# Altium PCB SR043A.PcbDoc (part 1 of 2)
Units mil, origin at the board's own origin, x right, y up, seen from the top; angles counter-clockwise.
Board outline 3937.01 x 3543.31 mil, 6 copper layers (Top Layer, Signal Layer 1, Signal Layer 2, Signal Layer 3, Signal Layer 4, Bottom Layer), stack 60.536 mil thick; 120 components, 36 nets, 230 pads, 513 vias.
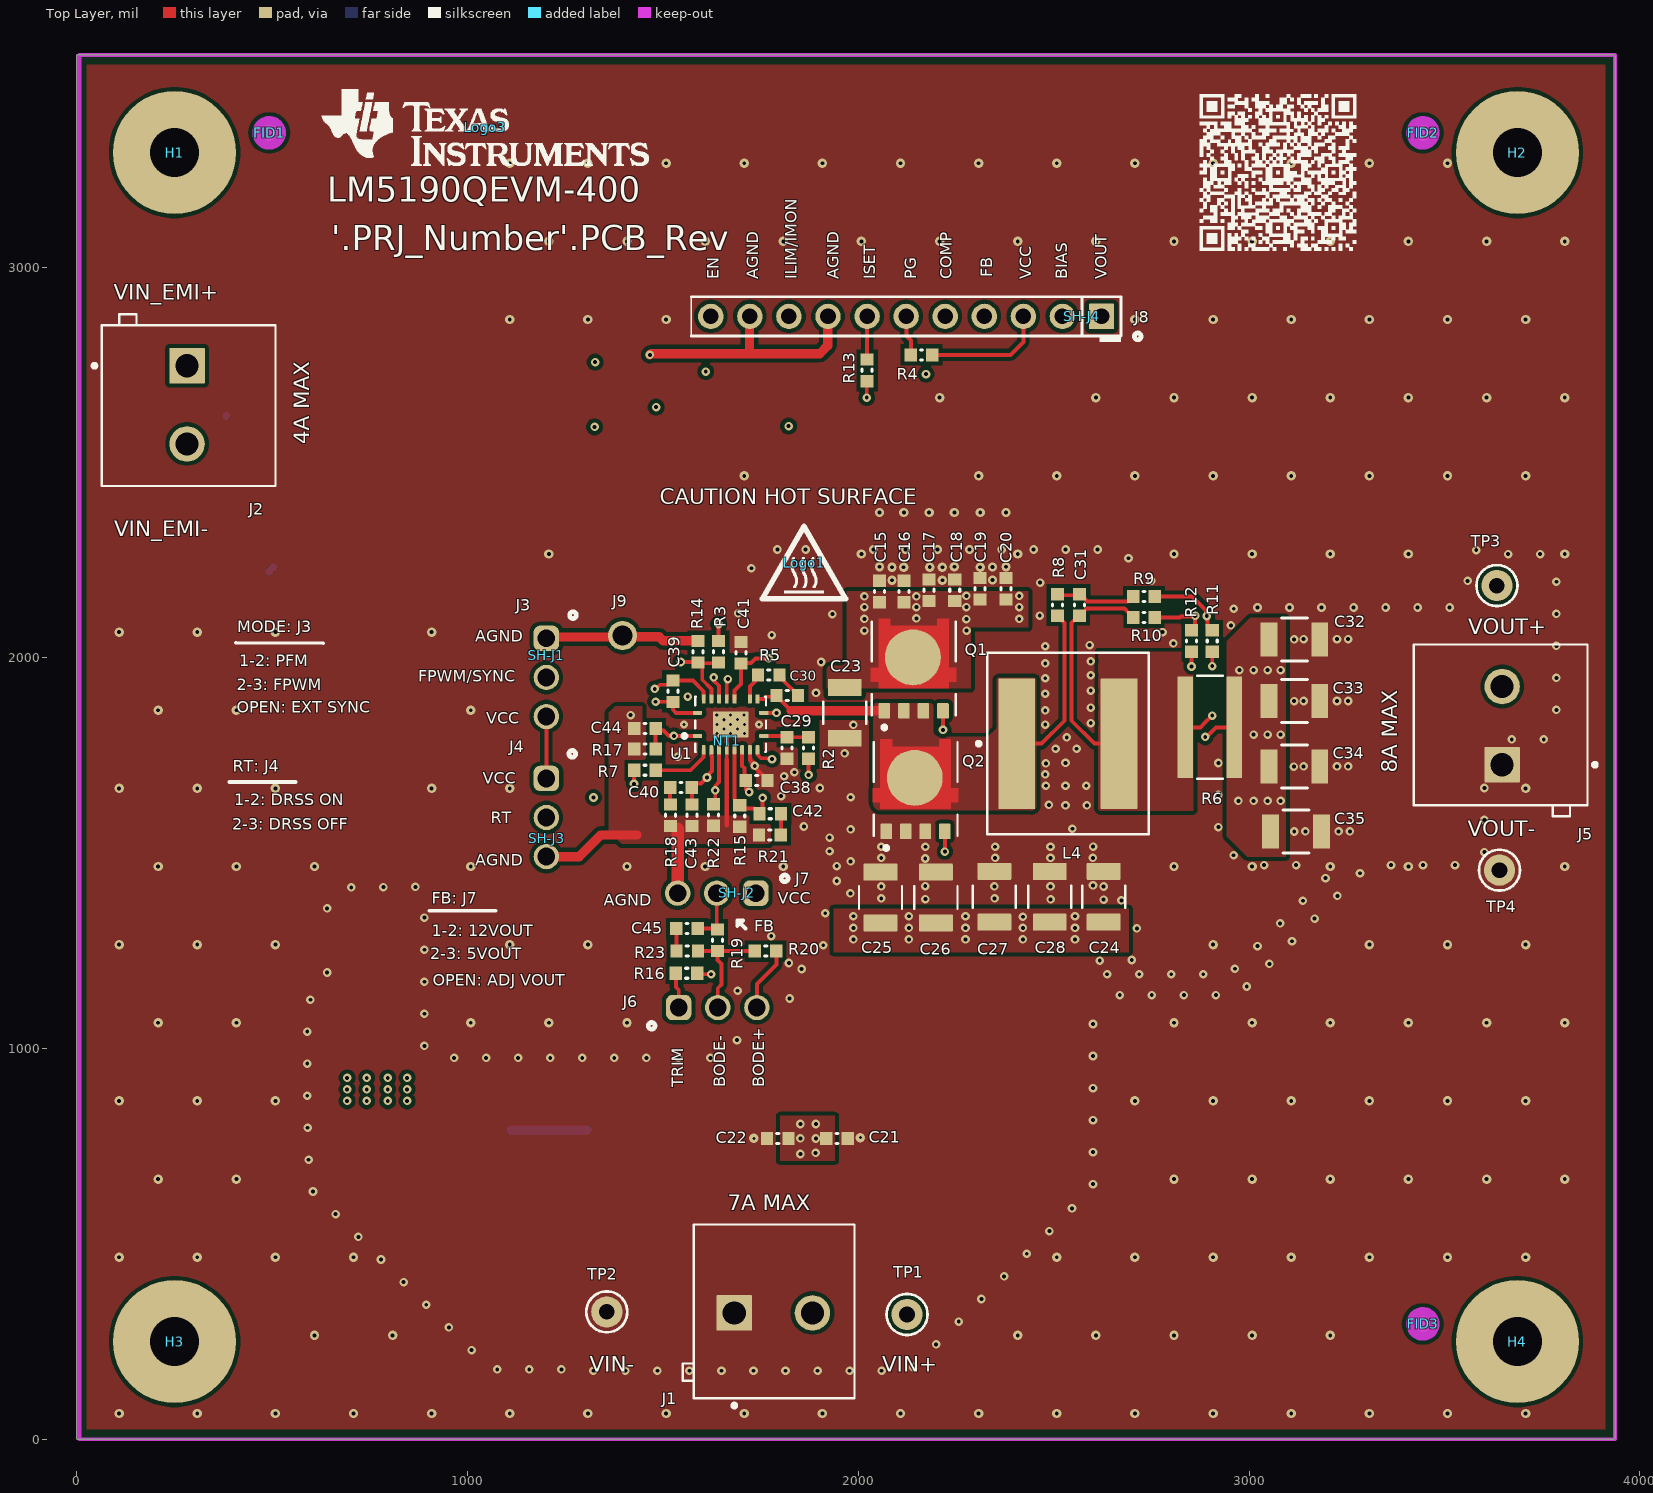
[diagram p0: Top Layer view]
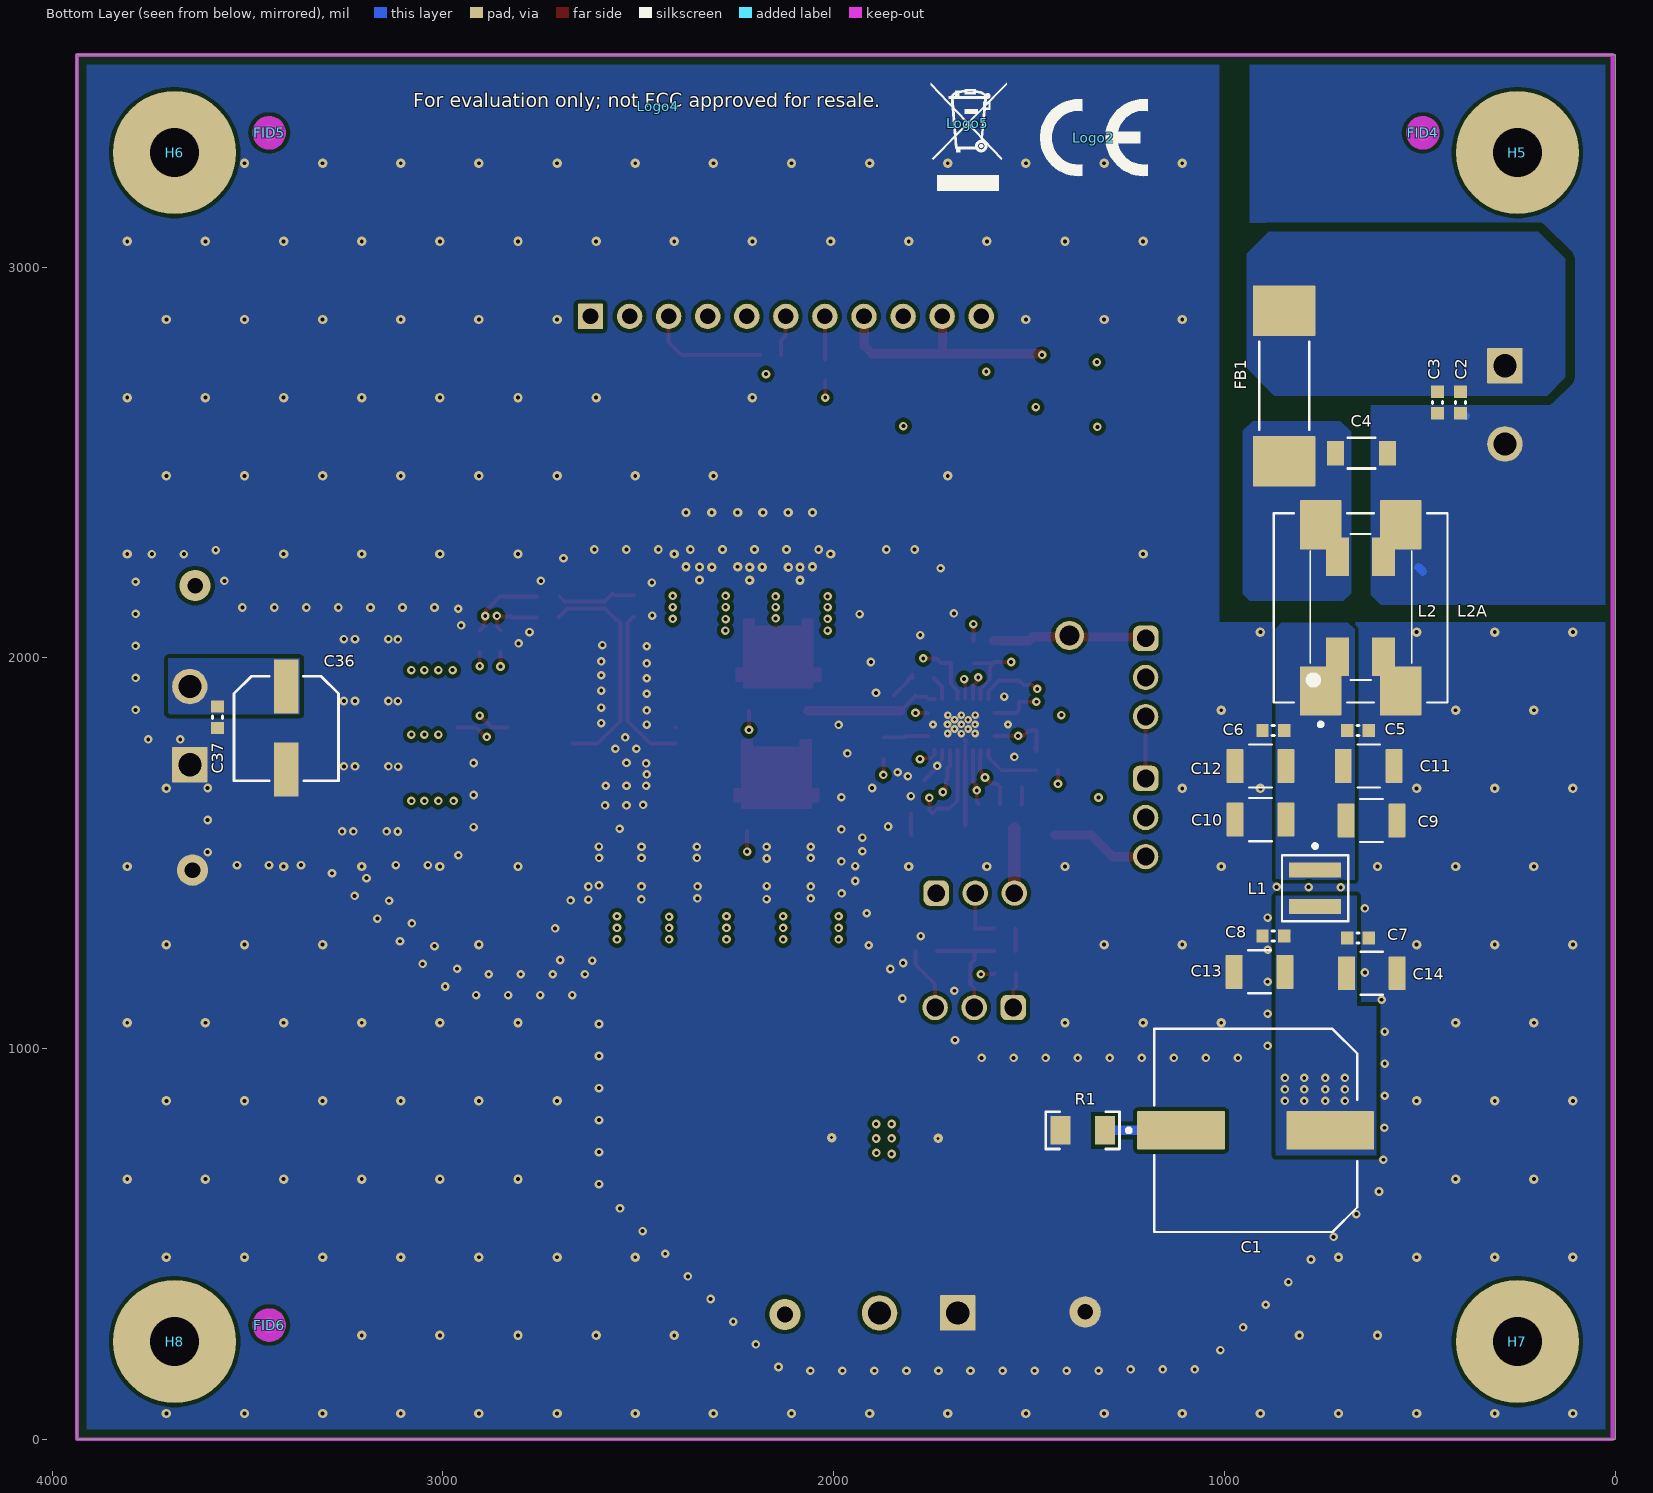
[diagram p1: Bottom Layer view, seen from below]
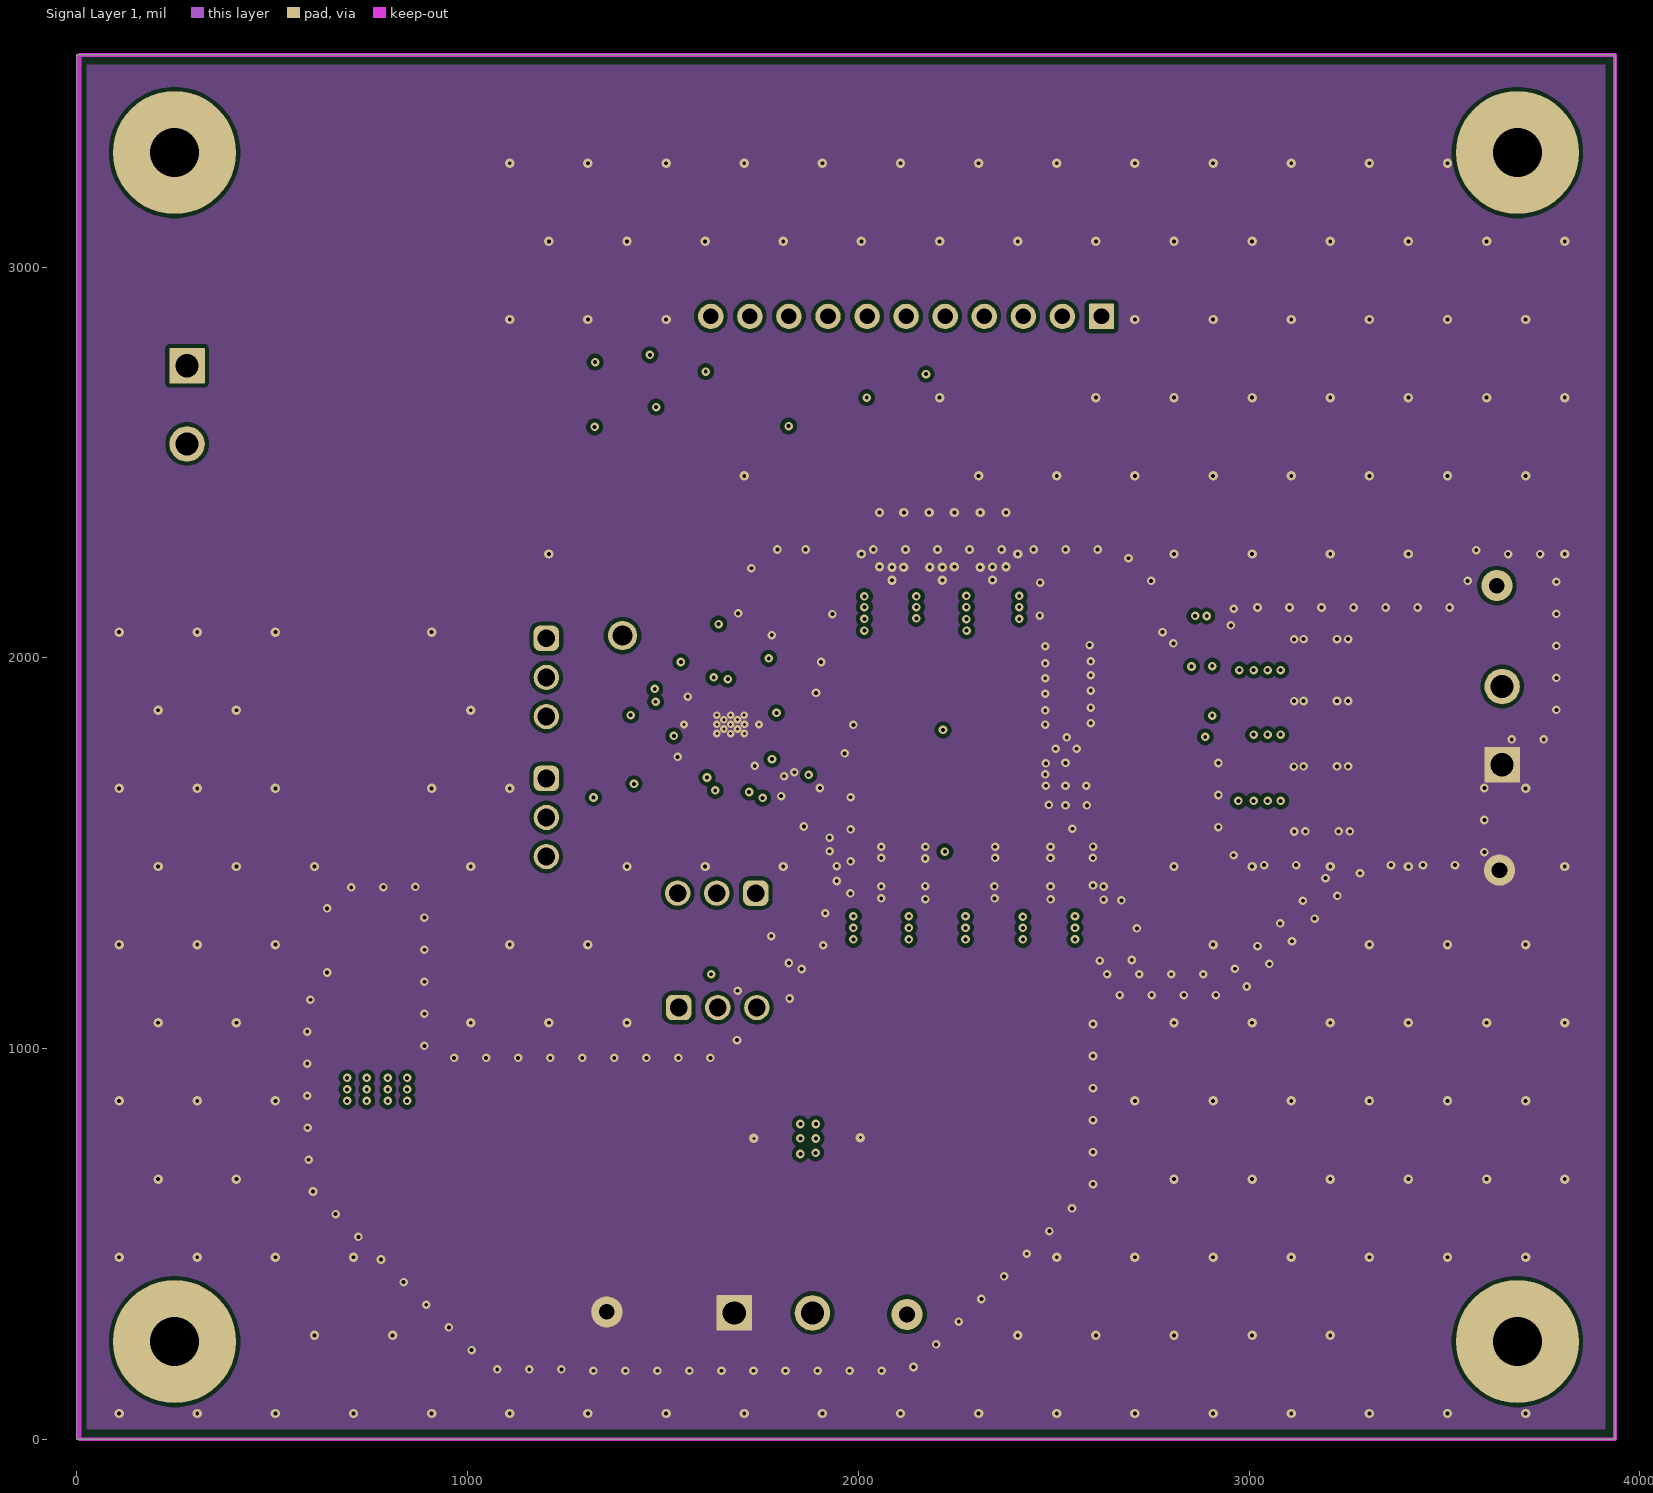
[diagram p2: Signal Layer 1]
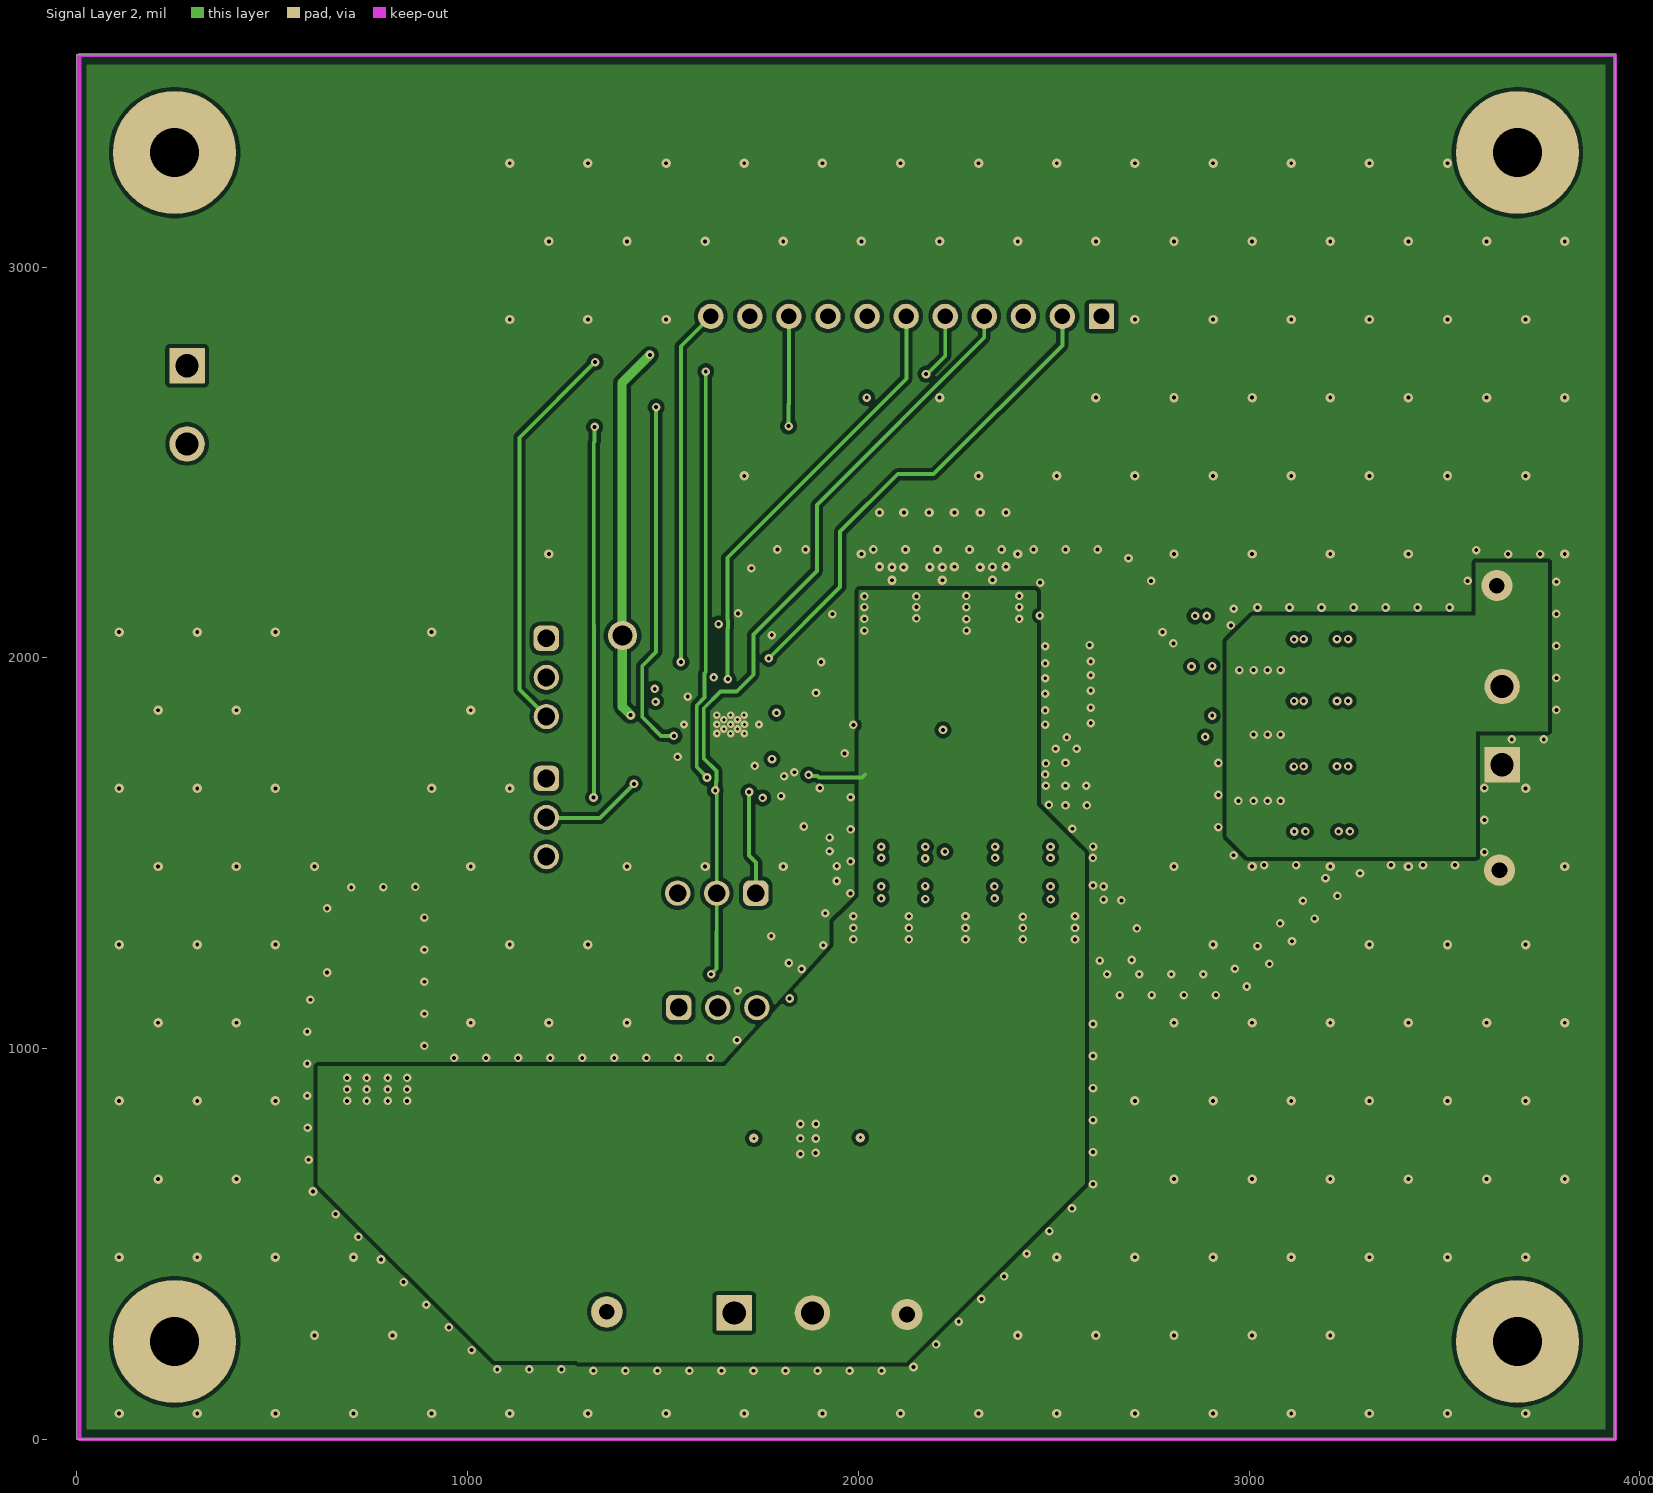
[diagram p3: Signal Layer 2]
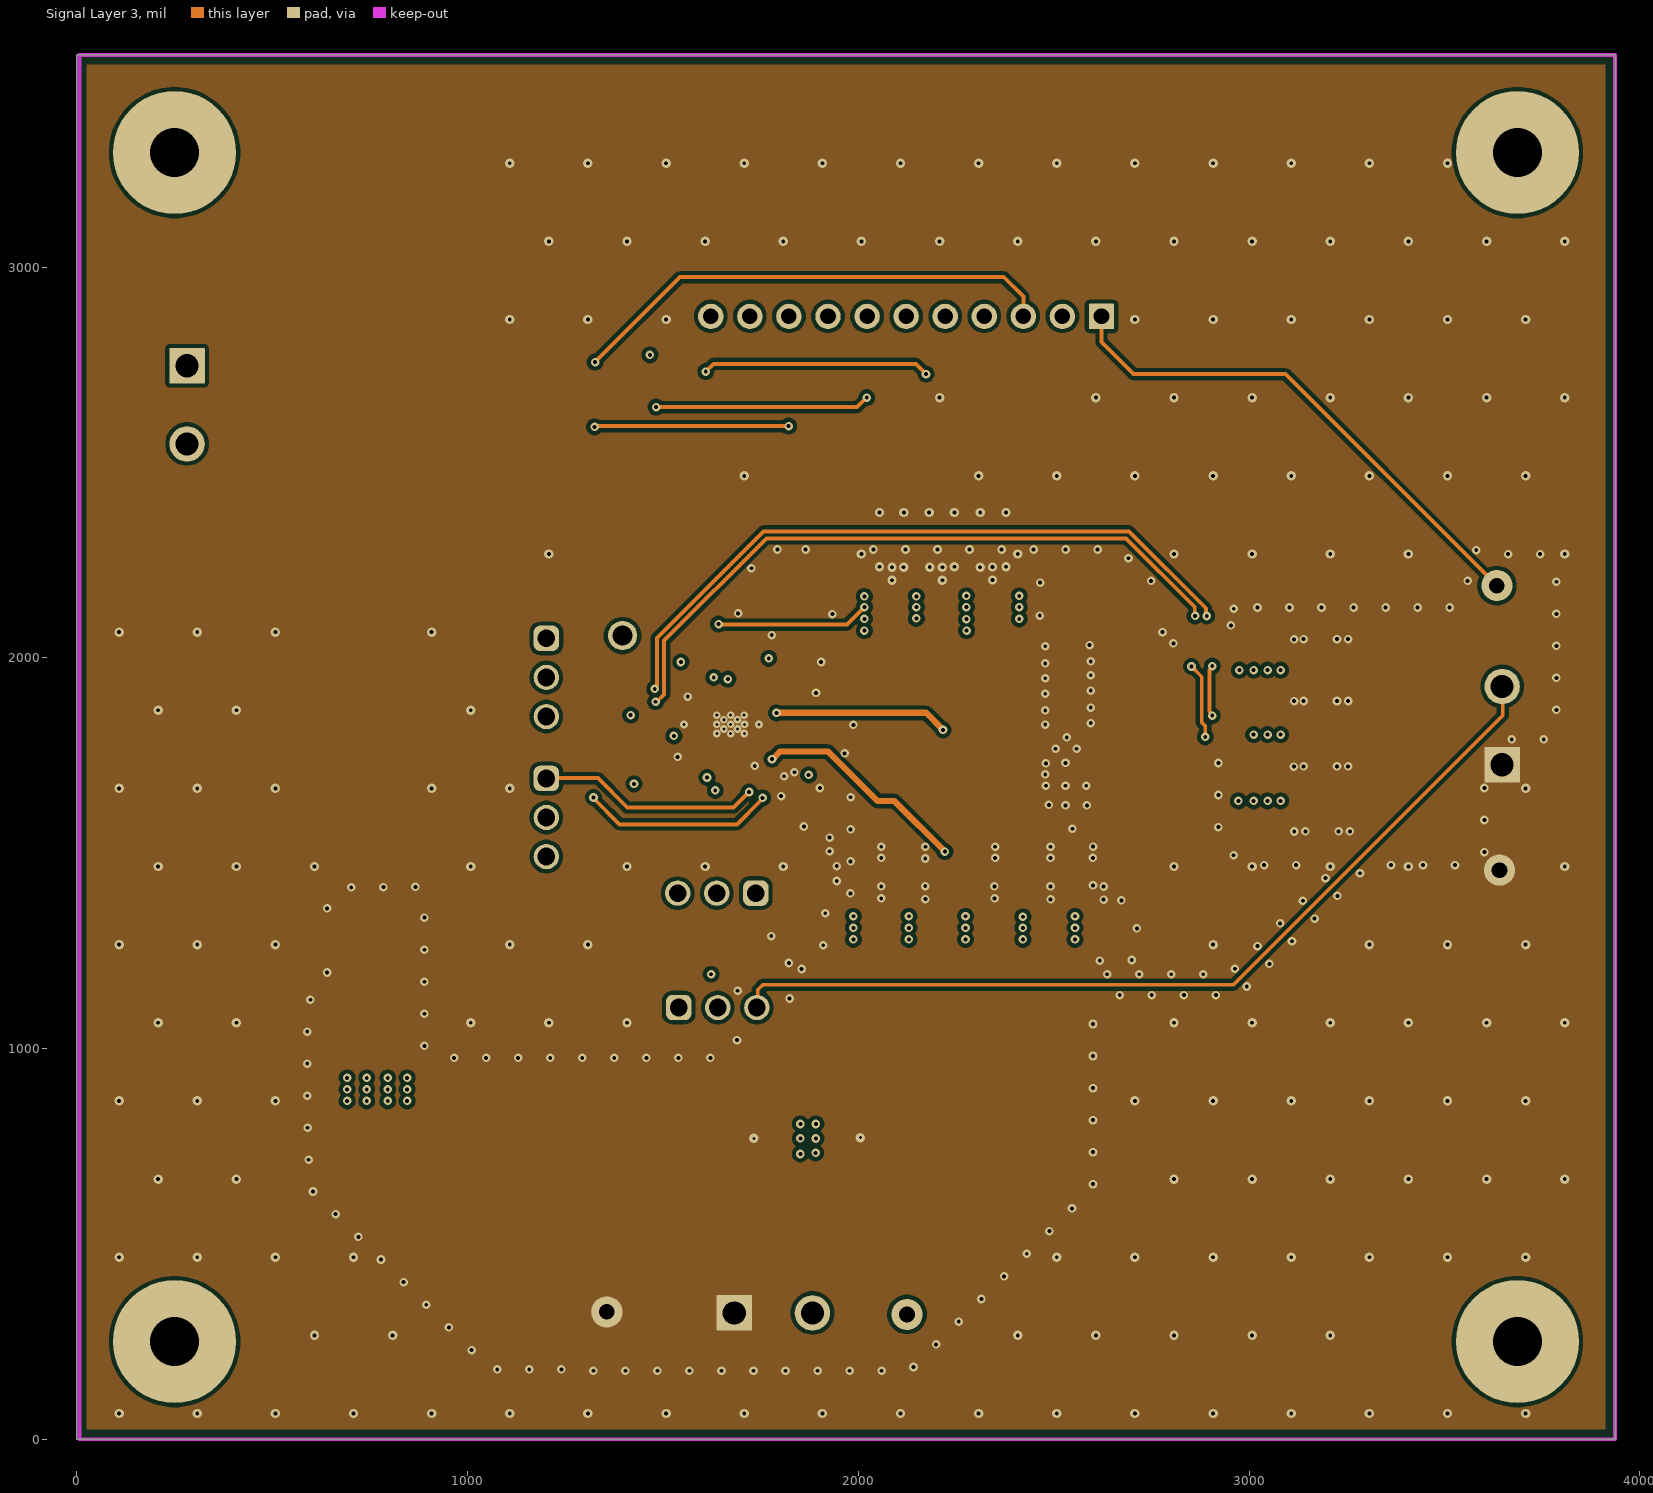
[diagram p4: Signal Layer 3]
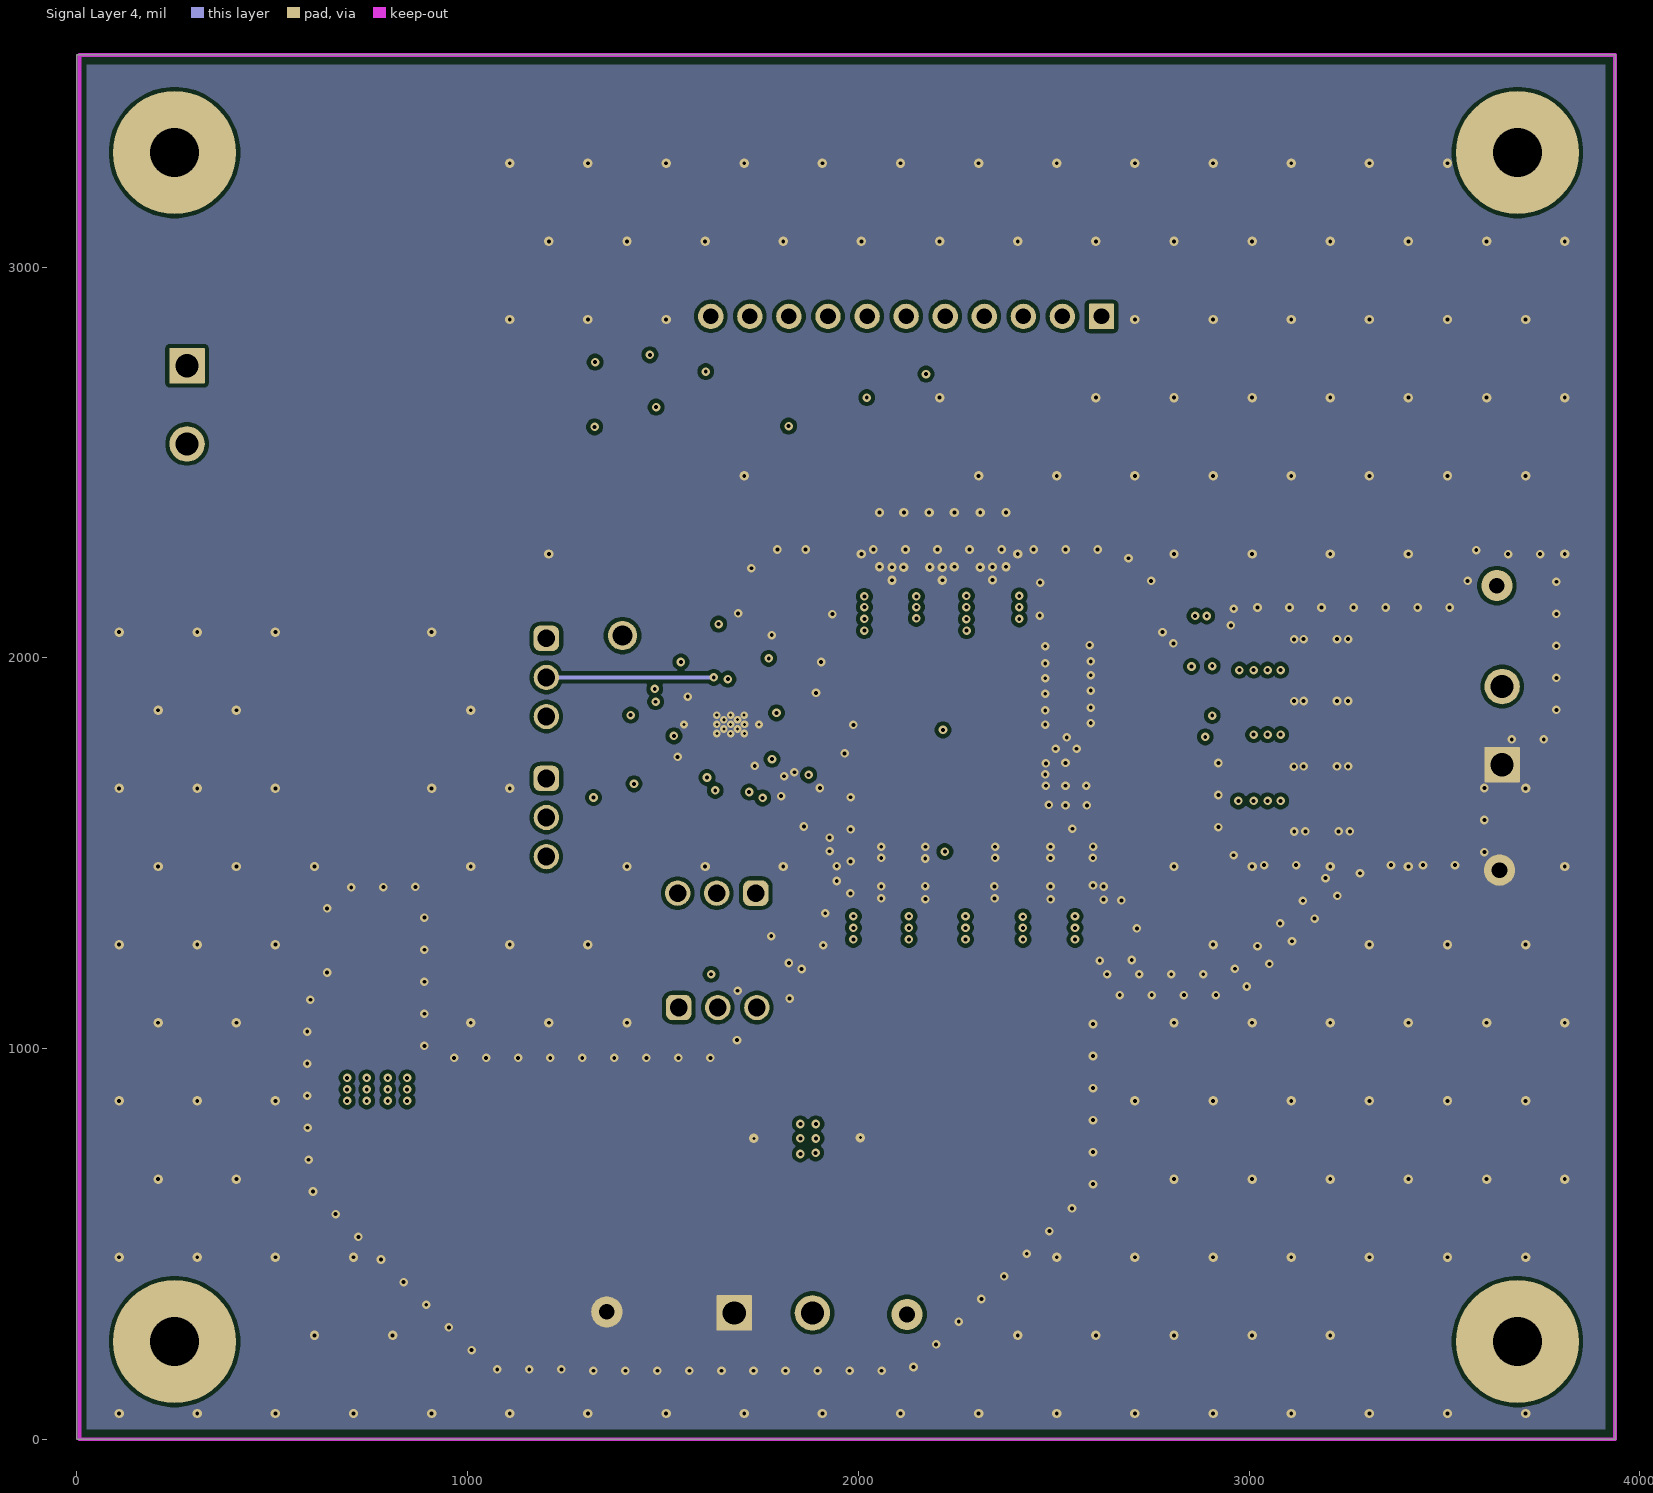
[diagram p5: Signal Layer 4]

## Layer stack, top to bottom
Top Solder: solder mask 0.4, Solder Resist, Dk 3.5
Top Layer: signal copper 2.756
Dielectric 1: prepreg 6, FR-4 High Tg, Dk 4.1
Signal Layer 1: signal copper 2.756
Dielectric 2: prepreg 10, FR-4 High Tg, Dk 4.1
Signal Layer 2: signal copper 2.756
Dielectric 3: core 12, FR-4 High Tg, Dk 4.8
Signal Layer 3: signal copper 2.756
Dielectric 4: prepreg 10, FR-4 High Tg, Dk 4.1
Signal Layer 4: signal copper 2.756
Dielectric 5: prepreg 6, FR-4 High Tg, Dk 4.1
Bottom Layer: signal copper 2.756
Bottom Solder: solder mask 0.4, Solder Resist, Dk 3.5

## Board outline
0,0 0,3543.31 3937.01,3543.31 3937.01,0

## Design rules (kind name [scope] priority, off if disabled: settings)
AcuteAngle [All] p1: minimum=4.50000000000000E+0001 checktracksonly=FALSE
AssemblyTestPointUsage [All] p1: valid=2
BoardOutlineClearance BoardOutlineClearance_MountingHoles [OnCopper and InComponentClass('Mounting Holes')] p1: gap=39.37 ignorepadtopadclearanceinfootprint=FALSE
BoardOutlineClearance BoardOutlineClearance_Poly [OnCopper and IsPoly] p2: gap=25 ignorepadtopadclearanceinfootprint=FALSE
BoardOutlineClearance [OnCopper and Not InComponentClass('Logo') and not InComponentClass('FiducialMark') and not InRegion(1000,500,4000,800) and not InPoly] p3: gap=40 ignorepadtopadclearanceinfootprint=FALSE
Clearance Clearance_1 [InNamedPolygon('BOTTOM_LAYER_VIN_EMI_P172')] p1: gap=24 ignorepadtopadclearanceinfootprint=FALSE
Clearance Clearance_Keepouts [((IsTrack Or IsArc) And Not InPoly) And IsFree and IsKeepOut vs ((IsTrack Or IsArc) And Not InPoly) And IsFree and IsKeepOut] p2: gap=0 ignorepadtopadclearanceinfootprint=FALSE
Clearance Clearance_Poly [InPolygon] p3: gap=10 ignorepadtopadclearanceinfootprint=TRUE
Clearance Clearance_FiducialMark [IsKeepOut and InComponentClass('FiducialMark') vs IsPad and InComponentClass('FiducialMark')] p4: gap=0 ignorepadtopadclearanceinfootprint=FALSE
Clearance [All] p5: gap=7.87 ignorepadtopadclearanceinfootprint=TRUE
ComponentClearance ComponentClearance_MountingHoles_FiducialMarks [InComponentClass('Mounting Holes') vs InComponentClass('FiducialMark')] p1: gap=50 collisioncheckmode=3 verticalgap=10 showdistances=FALSE
ComponentClearance ComponentClearance_Shunt [InComponentClass('Header') vs InComponentClass('Shunt')] p2: gap=0 collisioncheckmode=3 verticalgap=0 showdistances=FALSE
ComponentClearance ComponentClearance_Logo [InComponentClass('Logo')] p3: gap=30 collisioncheckmode=3 verticalgap=10 showdistances=FALSE
ComponentClearance ComponentClearance_ScrewToNut [(HasFootprint('NY PMS 440 0025 PH')) vs (HasFootprint('Keystone_1902E'))] p4: gap=5 collisioncheckmode=3 verticalgap=10 showdistances=FALSE
ComponentClearance ComponentClearance_MountingHoles [InComponentClass('Mounting Holes')] p5: gap=100 collisioncheckmode=3 verticalgap=100000 showdistances=FALSE
ComponentClearance ComponentClearance_SmallPassives [HasFootprint('0201*') or HasFootprint('0402*') or HasFootprint('0508') or HasFootprint('0603*') or HasFootprint('0612') or HasFootprint('0805*') or HasFootprint('0815*') or HasFootprint('0830*') or HasFootprint('1206*') or HasFootprint('1210*') or HasFootprint('1808*') or HasFootprint('1812*') or HasFootprint('1825*') or HasFootprint('2010*') or HasFootprint('2220*') or HasFootprint('2225*') or HasFootprint('2512*') or HasFootprint('2728*') or HasFootprint('3518*') vs HasFootprint('0201*') or HasFootprint('0402*') or HasFootprint('0508') or HasFootprint('0603*') or HasFootprint('0612') or HasFootprint('0805*') or HasFootprint('0815*') or HasFootprint('0830*') or HasFootprint('1206*') or HasFootprint('1210*') or HasFootprint('1808*') or HasFootprint('1812*') or HasFootprint('1825*') or HasFootprint('2010*') or HasFootprint('2220*') or HasFootprint('2225*') or HasFootprint('2512*') or HasFootprint('2728*') or HasFootprint('3518*')] p6: gap=14.96 collisioncheckmode=3 verticalgap=10 showdistances=FALSE
ComponentClearance ComponentClearance_THtoSMT_ShuntJumper [IsThruComponent vs HasFootprint('Harwin_M7582-05')] p7: gap=0 collisioncheckmode=3 verticalgap=0 showdistances=FALSE
ComponentClearance ComponentClearance_THtoSMT [IsThruComponent vs IsSMTComponent] p8: gap=15 collisioncheckmode=3 verticalgap=15 showdistances=FALSE
ComponentClearance ComponentClearance_THtoTH [IsThruComponent vs IsThruComponent] p9: gap=20 collisioncheckmode=3 verticalgap=30 showdistances=FALSE
ComponentClearance ComponentClearance_NetTie [HasFootprint('Net-Tie_10mil')] p10: gap=0 collisioncheckmode=3 verticalgap=0 showdistances=FALSE
ComponentClearance ComponentClearance_L2-L2A [HasFootprint('IND_TDK_ACM7060') vs HasFootprint('FP-744237701_SMT_CHOKE_12MM00_11MM00-MFG')] p11: gap=0 collisioncheckmode=3 verticalgap=0 showdistances=FALSE
ComponentClearance [All] p12: gap=20 collisioncheckmode=3 verticalgap=10 showdistances=FALSE
DiffPairsRouting [All] p1: maxlimit=100 minlimit=10 mostfreqgap=10 toplayer_minwidth=15 toplayer_maxwidth=15 toplayer_prefwidth=15 midlayer1_minwidth=15 midlayer1_maxwidth=15 midlayer1_prefwidth=15 midlayer2_minwidth=15 midlayer2_maxwidth=15 midlayer2_prefwidth=15 midlayer3_minwidth=15 midlayer3_maxwidth=15 midlayer3_prefwidth=15 midlayer4_minwidth=15 midlayer4_maxwidth=15 midlayer4_prefwidth=15 bottomlayer_minwidth=15 bottomlayer_maxwidth=15 bottomlayer_prefwidth=15 maxuncoupledlength=1000
FabricationTestPointUsage TestPointUsage [All] p1: valid=2 allowmultiple=FALSE
FabricationTestpoint Testpoint [All] p1: side=3 testpointundercomponent=TRUE minsize=40 maxsize=100 preferedsize=60 minholesize=0 maxholesize=40 preferedholesize=32 testpointgrid=1 allowsidetop=TRUE allowsidebottom=TRUE usegrid=TRUE gridtolerance=0.01
FanoutControl Fanout_LCC [IsLCC] p1: bgadir=Out bgaviamode=Centered fanoutstyle=Auto fanoutdirection=Alternating viagrid=1 // Fanout_LCC (Default Rule)
FanoutControl Fanout_BGA [IsBGA] p2: bgadir=Out bgaviamode=Centered fanoutstyle=Auto fanoutdirection=Alternating viagrid=1 // Fanout_BGA (Default Rule)
FanoutControl Fanout_Default [All] p4: bgadir=Out bgaviamode=Centered fanoutstyle=Auto fanoutdirection=Alternating viagrid=1 // Fanout_Default (Default Rule)
FanoutControl Fanout_Small [(CompPinCount < 5)] p5: bgadir=Out bgaviamode=Centered fanoutstyle=Auto fanoutdirection=OutThenIn viagrid=1 // Fanout_Small (Default Rule)
Height [All] p1: minheight=0 maxheight=2000 prefheight=500
HoleSize [All] p1: absolutevalues=TRUE maxlimit=251 minlimit=7.87 maxpercent=80.000 minpercent=20.000
MinimumAnnularRing MinimumAnnularRing_ThermalPadVias [IsVia and InAnyComponent] p1: minimumring=5.91
MinimumAnnularRing [All] p2: minimumring=5.9
MinimumSolderMaskSliver MinimumSolderMaskSliver_Logo [InComponentClass('Logo') vs InComponentClass('Logo')] p1: minsoldermaskwidth=0.7
MinimumSolderMaskSliver [All] p2: minsoldermaskwidth=3.94
PlaneConnect [All] p1: planeconnectstyle=Relief reliefexpansion=10 reliefentries=4 reliefconductorwidth=10 reliefairgap=10
PolygonConnect [All] p1: connectstyle=Direct reliefconductorwidth=10 reliefentries=4 polygonreliefangle="90 Angle" airgapwidth=10
RoutingVias ThermalPadVias [IsVia and InAnyComponent] p1: holewidth=7.87 width=19.68 viastyle="Through Hole" minholewidth=7.87 minwidth=19.68 maxholewidth=12.99 maxwidth=23.62
RoutingVias [All] p2: holewidth=10 width=22 viastyle="Through Hole" minholewidth=7.87 minwidth=19.68 maxholewidth=40 maxwidth=65
SilkToBoardRegionClearance [Not ((IsComment or IsDesignator) And (Hide <> 'False')) and not InRegion(1000,500,4000,800)] p1:
SilkToSilkClearance SilkToSilkClearance_Pb-FreeLogo [(HasFootprint('Pb-Free_Overlay_Medium') OR HasFootprint('Pb-Free_Overlay_Small')) vs (HasFootprint('Pb-Free_Overlay_Medium') OR HasFootprint('Pb-Free_Overlay_Small'))] p1: silktosilkclearance=0
SilkToSilkClearance [All] p2: silktosilkclearance=3.94
SilkToSolderMaskClearance SilkToComponentPadClearance [(IsPad or IsFill or IsRegion) and InAnycomponent] p1: minsilkscreentomaskgap=5 clearancetoexposedcopper=TRUE
SilkToSolderMaskClearance "Silk to Solder Mask Opening" [All] p2: minsilkscreentomaskgap=3.94 clearancetoexposedcopper=FALSE
SolderMaskExpansion [All] p1: expansion=1.97 istentingtop=FALSE
UnRoutedNet [All] p1: checkbadconnections=TRUE
Width [All] p1: maxlimit=100 minlimit=6 preferedwidth=10 checkconnectedcopper=TRUE
13 further rules are at their usual default settings.

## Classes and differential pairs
component class SR043A_Schematic: C1 C2 C3 C4 C5 C6 C7 C8 C9 C10 C11 C12 C13 C14 C15 C16 C17 C18 C19 C20 C21 C22 C23 C24 C25 C26 C27 C28 C29 C30 C31 C32 C33 C34 C35 C36 C37 C38 C39 C40 C41 C42 C43 C44 C45 FB1 J1 J2 J3 J4 J5 J6 J7 J8 J9 L1 L2 L2A L4 NT1 Q1 Q2 R1 R2 R3 R4 R5 R6 R7 R8 R9 R10 R11 R12 R13 R14 R15 R16 R17 R18 R19 R20 R21 R22 R23 TP1 TP2 TP3 TP4 U1
component class Header: J3 J4 J6 J7 J8
component class "Mounting Holes": H1 H2 H3 H4
component class Logo: Logo3
component class SR043A_Hardware: FID1 FID2 FID3 FID4 FID5 FID6 H1 H2 H3 H4 H5 H6 H7 H8 Logo1 Logo2 Logo3 Logo4 Logo5 SH-J1 SH-J2 SH-J3 SH-J4 ZZ1 ZZ2 ZZ3 ZZ4 ZZ5 ZZ6 ZZ7
component class FiducialMark: FID1 FID2 FID3 FID4 FID5 FID6
component class AssemblyNote: ZZ1 ZZ2 ZZ3 ZZ4 ZZ5 ZZ6 ZZ7

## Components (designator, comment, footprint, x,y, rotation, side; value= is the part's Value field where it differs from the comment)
C1 "EMVY101ARA101MKE0S" FP-EMVY101ARA101MKE0S_RADIAL-MFG 920.05,790.62 r180 bottom value=100µF
C2 "HMK107B7104MAHT" 0603L 395.35,2653.47 r270 bottom value=0.1uF
C3 "CGA3E2X7R2A223K080AA" 0603L 454.58,2653.65 r270 bottom value=0.022uF
C4 "CGA5L3X7S2A225M160AB" 1206_190 649.09,2523.96 r180 bottom value=2.2uF
C5 "CGA3E2X7R2A223K080AA" 0603L 658.26,1814.13 r180 bottom value=0.022uF
C6 "CGA3E2X7R2A223K080AA" 0603L 874.74,1814.42 r0 bottom value=0.022uF
C7 "HMK107B7104MAHT" 0603L 658.26,1282.91 r180 bottom value=0.1uF
C8 "HMK107B7104MAHT" 0603L 874.74,1288.68 r0 bottom value=0.1uF
C9 "CNC6P1X7R2A475K250AE" FP-CNC6P1X7R2A475K250AE_1210-MFG 623.47,1583.68 r0 bottom value=4.7µF
C10 "CNC6P1X7R2A475K250AE" FP-CNC6P1X7R2A475K250AE_1210-MFG 907.57,1585.99 r180 bottom value=4.7µF
C11 "CNC6P1X7R2A475K250AE" FP-CNC6P1X7R2A475K250AE_1210-MFG 630.94,1723.17 r0 bottom value=4.7µF
C12 "CNC6P1X7R2A475K250AE" FP-CNC6P1X7R2A475K250AE_1210-MFG 907.57,1723.17 r180 bottom value=4.7µF
C13 "CNC6P1X7R2A475K250AE" FP-CNC6P1X7R2A475K250AE_1210-MFG 910.18,1196.34 r180 bottom value=4.7µF
C14 "CNC6P1X7R2A475K250AE" FP-CNC6P1X7R2A475K250AE_1210-MFG 622.82,1192.8 r0 bottom value=4.7µF
C15 "885012206114" 0603L 2054.23,2170.16 r90 top value=0.01uF
C16 "885012206114" 0603L 2116.73,2170.16 r90 top value=0.01uF
C17 "885012206114" 0603L 2181.1,2172.96 r90 top value=0.01uF
C18 "885012206114" 0603L 2246.88,2172.96 r90 top value=0.01uF
C19 "885012206114" 0603L 2312.01,2177.05 r90 top value=0.01uF
C20 "885012206114" 0603L 2377.95,2177.05 r90 top value=0.01uF
C21 "HMK107B7104MAHT" 0603L 1945.22,769.95 r0 top value=0.1uF
C22 "HMK107B7104MAHT" 0603L 1793.62,769.95 r180 top value=0.1uF
C23 "CNC6P1X7R2A475K250AE" FP-CNC6P1X7R2A475K250AE_1210-MFG 1965.17,1859.25 r90 top value=4.7µF
C24 "CNC6P1X7R2A475K250AE" FP-CNC6P1X7R2A475K250AE_1210-MFG 2627.95,1388.53 r270 top value=4.7µF
C25 "CNC6P1X7R2A475K250AE" FP-CNC6P1X7R2A475K250AE_1210-MFG 2056.72,1386.56 r270 top value=4.7µF
C26 "CNC6P1X7R2A475K250AE" FP-CNC6P1X7R2A475K250AE_1210-MFG 2198.54,1386.56 r270 top value=4.7µF
C27 "CNC6P1X7R2A475K250AE" FP-CNC6P1X7R2A475K250AE_1210-MFG 2348.15,1388.53 r270 top value=4.7µF
C28 "CNC6P1X7R2A475K250AE" FP-CNC6P1X7R2A475K250AE_1210-MFG 2489.88,1388.53 r270 top value=4.7µF
C29 "HMK107C7224MAHTE" 0603L 1817.99,1769.18 r90 top value=0.22uF
C30 "HMK107B7104MAHT" 0603L 1818.11,1903.49 r0 top value=0.1uF
C31 "GCM188R72A472KA37D" 0603L 2566.47,2135.44 r270 top value=4700pF
C32 "C1210C226K3RAC7800" 1210_280 3116.14,2047.14 r0 top value=22uF
C33 "C1210C226K3RAC7800" 1210_280 3116.14,1889.66 r0 top value=22uF
C34 "C1210C226K3RAC7800" 1210_280 3116.14,1722.34 r0 top value=22uF
C35 "C1210C226K3RAC7800" 1210_280 3120.08,1555.82 r0 top value=22uF
C36 "EMVH250ADA330MF60G" CAPSMT_62_F60 3401.57,1821.03 r270 bottom value=33uF
C37 "HMK107B7104MAHT" 0603L 3577.04,1848.18 r270 bottom value=0.1uF
C38 "CGA3E1X7S1C225M080AC" 0603L 1739.78,1686.62 r0 top value=2.2uF
C39 "GRM1885C2A101JA01D" 0603L 1525.31,1914.47 r90 top value=100pF
C40 "C0603C123J3GACTU" 0603L 1545.98,1667.92 r180 top value=0.012uF
C41 "06033C105KAT2A" 0603L 1699.42,2013.07 r90 top value=1uF
C42 "885012206114" 0603L 1774.46,1601.08 r0 top value=0.01uF
C43 "CGA3E2NP01H470J080AA" 0603L 1574.53,1597.29 r270 top value=47pF
C44 "HMK107B7104MAHT" 0603L 1453.84,1819.13 r0 top value=0.1uF
C45 "GRM1885C1E681JA01D" 0603L 1561.73,1307.09 r0 top value=680pF
FB1 "78279225101" FP-78279225101_3312-MFG 847.18,2695.93 r270 bottom
FID1 "Fiducial" Fiducial10-20 492.13,3343.8 r0 top
FID2 "Fiducial" Fiducial10-20 3444.88,3343.8 r0 top
FID3 "Fiducial" Fiducial10-20 3444.88,295.28 r0 top
FID4 "Fiducial" Fiducial10-20 492.13,3343.8 r180 bottom
FID5 "Fiducial" Fiducial10-20 3444.88,3343.8 r180 bottom
FID6 "Fiducial" Fiducial10-20 3444.88,292.49 r180 bottom
H1 "NY PMS 440 0025 PH" "NY PMS 440 0025 PH" 250,3293.31 r0 top
H2 "NY PMS 440 0025 PH" "NY PMS 440 0025 PH" 3687.01,3293.31 r0 top
H3 "NY PMS 440 0025 PH" "NY PMS 440 0025 PH" 250,250 r0 top locked
H4 "NY PMS 440 0025 PH" "NY PMS 440 0025 PH" 3687.01,250 r0 top
H5 "1902E" Keystone_1902E 250,3293.31 r180 bottom
H6 "1902E" Keystone_1902E 3687.01,3293.31 r180 bottom
H7 "1902E" Keystone_1902E 250,250 r180 bottom locked
H8 "1902E" Keystone_1902E 3687.01,250 r180 bottom
J1 "691253510002" FP-691253510002_CONN_TERM_BLOCK2-MFG 1770.73,327.44 r0 top
J2 "691253510002" FP-691253510002_CONN_TERM_BLOCK2-MFG 286.04,2659.45 r270 top
J3 "61300311121" WURTH_61300311121 1201.57,1949.89 r270 top
J4 "61300311121" WURTH_61300311121 1201.57,1591.43 r270 top
J5 "691253510002" FP-691253510002_CONN_TERM_BLOCK2-MFG 3644.05,1814.71 r90 top
J6 "61300311121" WURTH_61300311121 1640.33,1105.01 r0 top
J7 "61300311121" WURTH_61300311121 1637.67,1397.83 r180 top
J8 "TSW-111-07-G-S" TSW-111-07-G-S 2122.44,2874.02 r180 top
J9 "1040" CONN_1040 1396.6,2057.09 r90 top
L1 "XGL4040-222MEC" FP-XGL4040-222MEC_SMT2_4MM0_4MM0-MFG 767.94,1410.17 r270 bottom value=2.2uH
L2 "ACM70V-701-2PL-TL00" IND_TDK_ACM7060 651.37,2130.4 r90 bottom
L2A "744237701" FP-744237701_SMT_CHOKE_12MM00_11MM00-MFG 651.37,2127.97 r90 bottom
L4 "XGL1060-682MEC" FP-XGL1060-682MEC_SMT_IND_10MM0_11MM3-MFG 2536.38,1780.51 r0 top value=6.8uH
Logo1 "CAUTION HOT SURFACE" IEC_HotSurface_Small 1861.04,2244.05 r0 top
Logo2 "CE Mark" CE_Mark_5mm 1333.92,3331.43 r180 bottom
Logo3 "Texas Instruments" TI_Stacked_Overlay_Small 1045.67,3357.6 r0 top
Logo4 "FCC disclaimer" FCC_disclaimer 2448.52,3412.22 r180 bottom
Logo5 "WEEE logo" WEEE_Minimum 1656.43,3368.14 r180 bottom
NT1 "Net-Tie" Net-Tie_10mil 1663.39,1788.13 r270 top net-tie
Q1 "NTMFS6H848NT1G" FP-NTMFS6H848NT1G_DFN5-MFG 2141.73,1972.44 r0 top
Q2 "NTMFS6H848NT1G" FP-NTMFS6H848NT1G_DFN5-MFG 2146.48,1663.98 r0 top
R1 "RCA12060000ZSEA" 1206 1362.88,790.62 r0 bottom value=0
R2 "RC0603JR-070RL" 0603L 1872.94,1769.18 r270 top value=0
R3 "RC0603FR-07100KL" 0603L 1642.51,2015.87 r90 top value=100k
R4 "RC0603FR-07100KL" 0603L 2162.03,2775.59 r0 top value=100k
R5 "RC0603JR-070RL" 0603L 1770.87,1956.5 r0 top value=0
R6 "FCSL64R005FER" 2512_WIDE 2899.61,1821.95 r0 top value=0.005
R7 "RC0603FR-0754K9L" 0603L 1453.84,1712.29 r180 top value=54.9k
R8 "CRCW0603110KFKEA" 0603L 2509.65,2135.44 r90 top value=110k
R9 "ERJ-3EKF49R9V" 0603L 2731.5,2157.06 r180 top value=49.9
R10 "ERJ-3EKF49R9V" 0603L 2731.5,2103.12 r180 top value=49.9
R11 "ERJ-3EKF49R9V" 0603L 2905.91,2042.97 r90 top value=49.9
R12 "RC0603JR-070RL" 0603L 2852.78,2042.97 r270 top value=0
R13 "RC0603FR-074K99L" 0603L 2022.44,2735.89 r270 top value=4.99k
R14 "RC0603FR-078K87L" 0603L 1589.95,2015.87 r270 top value=8.87k
R15 "RC0603FR-079K53L" 0603L 1696.52,1595.35 r90 top value=9.53k
R16 "RC0603FR-072K67L" 0603L 1560.58,1192.73 r180 top value=2.67k
R17 "RC0603FR-0738K3L" 0603L 1453.84,1766.52 r0 top value=38.3k
R18 "RC0603FR-075K9L" 0603L 1519.73,1597.29 r90 top value=5.90k
R19 "RC0603FR-07100KL" 0603L 1639.31,1277.09 r270 top value=100k
R20 "M55342K12B49D9T" 0603L 1762.78,1249.53 r0 top value=49.9
R21 "RC0603JR-070RL" 0603L 1773.59,1546.62 r180 top value=0
R22 "RC0603FR-077K15L" 0603L 1629.71,1598.12 r90 top value=7.15k
R23 "RC0603JR-071KL" 0603L 1562.39,1249.8 r0 top value=1.0k
SH-J1 "M7582-05" Harwin_M7582-05 1201.57,2006.95 r90 top
SH-J2 "M7582-05" Harwin_M7582-05 1688.9,1398.56 r180 top
SH-J3 "M7582-05" Harwin_M7582-05 1202.06,1538.54 r90 top
SH-J4 "M7582-05" Harwin_M7582-05 2572.44,2874.02 r180 top
TP1 "5000" Keystone5000 2124.7,319.55 r0 top
TP2 "5001" Keystone5001 1356.3,326.13 r90 top
TP3 "5000" Keystone5000 3634.54,2185.04 r0 top
TP4 "5001" Keystone5001 3641.12,1456.69 r90 top
U1 "LM5190-Q1" RGY0019B-MFG 1673.23,1829.73 r90 top
ZZ1 "These assemblies are ESD sensitive, ESD precautions shall be observed." AssemblyNote 185,4263.39 r0 top
ZZ2 "These assemblies must be clean and free from flux and all contaminants. Use of no clean flux is not acceptable." AssemblyNote 185,4174.8 r0 top
ZZ3 "These assemblies must comply with workmanship standards IPC-A-610 Class 2, unless otherwise specified." AssemblyNote 185,4086.22 r0 top
ZZ4 "Install Shunt Jumper SH-J1 onto J3 (MODE) pins 2 - 3" AssemblyNote 185,3987.8 r0 top
ZZ5 "Install Shunt Jumper SH-J2 onto J4 (RT) pins 2 - 3" AssemblyNote 185,3899.21 r0 top
ZZ6 "Install Shunt Jumper SH-J3 onto J7 (FB) pins 1 - 2" AssemblyNote 185,3800.79 r0 top
ZZ7 "Install Shunt Jumper SH-J4 onto J8 (BIAS-VOUT) pins 1 - 2" AssemblyNote 185,3702.36 r0 top

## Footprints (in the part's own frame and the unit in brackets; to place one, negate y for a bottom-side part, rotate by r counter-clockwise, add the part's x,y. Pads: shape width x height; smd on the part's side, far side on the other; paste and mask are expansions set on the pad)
0603L [mm] "0603 from SM-752 data"
  rect 0.8x0.85 smd: 1(-0.7,0) 2(0.7,0)
  silkscreen extent -0.07,-0.33 0.07,0.33, body extent -0.87,-0.47 0.87,0.47, height 1
1206 [mm] "1206 from SM-752 data"
  rect 1.3x1.85 smd: 1(-1.45,0) 2(1.45,0)
  silkscreen extent -2.4,-1.21 2.4,1.21, body extent -1.7,-0.9 1.7,0.9, height 1.35
1206_190 [mm] "1206_190"
  rect 1.1x1.6 smd: 1(-1.7,0) 2(1.7,0)
  silkscreen extent -0.9,-1 0.9,1, body extent -1.75,-0.95 1.75,0.95, height 1.9
1210_280 [mm] "SMD, 2-Leads, Body 3.6x2.8mm, Height 2.8mm"
  rect 1.1x2.2 smd: 1(-1.65,0) 2(1.65,0)
  silkscreen extent -0.84,-1.4 0.84,1.4, body extent -1.8,-1.4 1.8,1.4, height 2.8
2512_WIDE [mm] "Ohmite recommended land pattern"
  rect 1x6.6 smd: 1(-1.6,0) 2(1.6,0)
  silkscreen extent -0.82,-3.32 0.82,3.35, body extent -1.65,-3.25 1.65,3.25, height 0.7
AssemblyNote [mil] "Assembly Note"
CAPSMT_62_F60 [mm] "6.3 x 5.7mm:  Chemi-Con F60"
  rect 3.5x1.6 smd: 1(-2.688,0.012) 2(2.712,0.012)
  silkscreen extent -3.35,-3.39 3.45,3.41, body extent -3.39,-3.39 3.45,3.41, height 6
CE_Mark_5mm [mil] "Minimum text height for CE Mark"
  silkscreen extent -138,-98 138,98
CONN_1040 [mil] "Test Point, PC  test point Terminal"
  round 75 hole 52: 1(0,0)
  body extent -55,-12 55,13, height 276
FCC_disclaimer [mil]
Fiducial10-20 [mm]
  round 1 smd mask+0.5: 1(0,0)
  Top Layer keep-out circle w1.178: c0,0 r0.5
FP-744237701_SMT_CHOKE_12MM00_11MM00-MFG [mm]
  rrect4% 3.2x2.7 smd paste+0 mask+0: 1(-5.4,2.6) 2(5.4,2.6) 3(-5.4,-2.6) 4(5.4,-2.6)
  silkscreen extent -7.7,-5.65 6.15,5.65, body extent -6.15,-5.5 6.15,5.5, height 6
FP-78279225101_3312-MFG [mm]
  rrect3% 3.3x4.06 smd paste+0 mask+0: 1(-4.89,0) 2(4.89,0)
  silkscreen extent -2.87,-1.63 2.87,1.63, body extent -4.25,-1.53 4.25,1.53, height 2.48
FP-691253510002_CONN_TERM_BLOCK2-MFG [mm]
  rrect4% 2.3x2.3 hole 1.5 paste-2539.97 mask+0: 1(-2.24,-0.1)
  round 2.3 hole 1.5 paste-2539.97 mask+0: 2(2.84,-0.1)
  silkscreen extent -5.58,-6.25 5.58,5.65, body extent -5.68,-5.75 5.68,5.75, height 0.25
FP-CNC6P1X7R2A475K250AE_1210-MFG [mm]
  rrect9% 1.1x2.2 smd paste+0 mask+0: 1(-1.65,0) 2(1.65,0)
  silkscreen extent -0.72,-1.4 0.72,1.4, body extent -1.6,-1.25 1.6,1.25, height 2.81
FP-EMVY101ARA101MKE0S_RADIAL-MFG [mm]
  rrect4% 5.7x2.5 smd paste+0 mask+0: 1(-4.85,0) 2(4.85,0)
  silkscreen extent -8.37,-6.6 6.6,6.6, body extent -6.85,-6.5 6.85,6.5, height 13.8
FP-NTMFS6H848NT1G_DFN5-MFG [mm]
  rrect13% 0.75x1 smd paste+0 mask+0: 1(-1.905,-2.748) 2(-0.635,-2.748) 3(0.635,-2.748) 4(1.905,-2.748)
  round 3.631 smd paste+0 mask+0: 5-6(-0.05,0.735)
  Top Layer region: -2.28,-1.282 -2.28,-0.857 -2.775,-0.857 -2.775,0.048 -2.28,0.048 -2.28,3.247 -1.53,3.247 -1.53,2.772 1.53,2.772 1.53,3.247 2.28,3.247 2.28,0.048 2.775,0.048 2.775,-0.857 2.28,-0.857 2.28,-1.282
  silkscreen extent -2.73,-3.95 2.73,3.05, body extent -2.88,-3.35 2.88,3.35, height 0.25
FP-XGL1060-682MEC_SMT_IND_10MM0_11MM3-MFG [mm]
  rrect4% 2.38x8.5 smd paste+0 mask+0: 1(-3.325,0) 2(3.325,0)
  silkscreen extent -5.92,-5.9 5.25,5.9, body extent -5.35,-6 5.35,6, height 0.25
FP-XGL4040-222MEC_SMT2_4MM0_4MM0-MFG [mm]
  rrect10% 0.98x3.4 smd paste+0 mask+0: 1(-1.185,0) 2(1.185,0)
  silkscreen extent -2.87,-2.15 2.15,2.15, body extent -2,-2 2,2, height 4.1
Harwin_M7582-05 [mil] "Single Operation 2.54mm Pitch Open Top Jumper Socket"
  body extent -98,-47 98,47, height 236
IEC_HotSurface_Small [mil]
  silkscreen extent -107,-93 107,92
IND_TDK_ACM7060 [mm] "TDK Common Mode EMI Filter 7mmx6mm"
  rect 2.5x1.5 smd: 1(-3.25,1.5) 2(-3.25,-1.5) 3(3.25,-1.5) 4(3.25,1.5)
  silkscreen extent -5,-3.32 4.75,3.32, body extent -3.6,-3.12 3.6,3.07, height 3.55
Keystone5000 [mil] "For Keystone 500x miniature loop terminals"
  round 80 hole 40: 1(0,0)
  silkscreen extent -52,-52 52,52, body extent -49,-49 49,49, height 182
Keystone5001 [mil] "For Keystone 500x miniature loop terminals"
  round 80 hole 40: 1(0,0)
  silkscreen extent -52,-52 52,52, body extent -49,-49 49,49, height 182
Keystone_1902E [mil] "Hex Standoff, 4-40 threaded, nylon"
  round 1 on Mech4: 0(0,0)
  body extent -145,-126 146,126, height 1001
Net-Tie_10mil [mil] "10mil net tie, no solder mask opening, no solder paste"
  rect 10x10 smd paste-5 mask-5: 1(-10,0) 2(10,0)
  Top Layer region: -6,5 6,5 6,-5 -6,-5
"NY PMS 440 0025 PH" [mm] "4-40 nylon screw and mounting hole"
  round 8 hole 3.2: 1(0,0)
  body extent -3.3,-3.3 3.3,3.3, height 2.69
RGY0019B-MFG [mm]
  rrect40% 0.25x0.6 smd paste+0 mask+0: 1(-0.75,2.15) 10(-0.75,-2.15) 11(0.75,-2.15) 19(0.75,2.15)
  rrect40% 0.6x0.25 smd paste+0 mask+0: 2(-1.65,1.75) 3(-1.65,1.25) 4(-1.65,0.75) 5(-1.65,0.25) 6(-1.65,-0.25) 7(-1.65,-0.75) 8(-1.65,-1.25) 9(-1.65,-1.75) 12(1.65,-1.75) 13(1.65,-1.25) 14(1.65,-0.25) 15(1.65,0.25) 16(1.65,0.75) 17(1.65,1.25) 18(1.65,1.75)
  rrect6% 1.7x2.3 smd paste-1000 mask+0: 20(0,0)
  silkscreen extent -1.8,-2.3 1.8,3.12, body extent -2.05,-2.55 2.05,2.55, height 0.25
TI_Stacked_Overlay_Small [mil]
  silkscreen extent -418,-98 418,98
TSW-111-07-G-S [mm] "Samtec 100mil, 1x11, 230 mil above insulator"
  rrect6% 1.65x1.65 hole 1.016: 1(-12.7,0)
  round 1.65 hole 1.016: 2(-10.16,0) 3(-7.62,0) 4(-5.08,0) 5(-2.54,0) 6(0,0) 7(2.54,0) 8(5.08,0) 9(7.62,0) 10(10.16,0) 11(12.7,0)
  silkscreen extent -13.97,-1.27 13.97,1.65, body extent -13.97,-1.27 13.97,1.27, height 8.38
WEEE_Minimum [mil] "WEEElie bin"
  silkscreen extent -95,-172 99,104
WURTH_61300311121 [mm] "Header, 2.54mm, 3x1, TH"
  rrect50% 1.65x1.65 hole 1.15: 1(-2.54,0)
  round 1.65 hole 1.15: 2(0,0) 3(2.54,0)
  body extent -3.81,-1.27 3.81,1.27, height 8.54

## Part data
C1: library part CMP-0094051-1, "100uF 100V 20% Aluminum Electrolytic Capacitors Radial, Can - SMD - 5000 Hrs @ 105°C", Digikey Part Number=565-2511-1-ND, Leakage Current=100uA, Manufacturer="United Chemi-Con", Mouser Part Number=661-EMVY101ARA101MKE, Operating Temperature Range="-40°C to +105°C", Tolerance_%=20%, ValueDisplayed=100uF
C2 C7 C8 C21 C22 C30 C37 C44: library part CMP-0078500-1, "CAP, CERM, 0.1 µF,  VAC/100 VDC,+/- 20%, X7R, AEC-Q200 Grade 1, 0603", Cap_Case=0603, Manufacturer="Taiyo Yuden", Supplier Part Number 1=587-5544-1-ND, TempCo=X7R, Tolerance_%=20%, Value2=100V, ValueDisplayed=0.1µF
C3 C5 C6: library part CMP-0007086-4, "CAP, CERM, 0.022 uF, 100 V, +/- 10%, X7R, AEC-Q200 Grade 1, 0603", Cap_Case=0603, Manufacturer=TDK, Supplier Part Number 1=445-5814-1-ND, TempCo=X7R, Tolerance_%=10%, Value1="0.083542 ohm", Value2=100V, ValueDisplayed=0.022uF
C4: library part CMP-0008791-2, "CAP, CERM, 2.2 uF, 100 V, +/- 20%, X7S, AEC-Q200 Grade 1, 1206_190", Cap_Case=1206, Manufacturer=TDK, Supplier Part Number 1=445-12947-1-ND, TempCo=X7S, Tolerance_%=20%, Value1=Unknown, Value2=100V, ValueDisplayed=2.2uF
C9 C10 C11 C12 C13 C14 C23 C24 C25 C26 C27 C28: library part CMP-0094503-1, "4.7 µF ±10% 100V Ceramic Capacitor X7R 1210 (3225 Metric)", Digikey Part Number=445-181657-1-ND, Manufacturer=TDK, Mouser Part Number=810-CNC6P1X7R2A475K2, Operating Temperature Range="-55°C to +125°C", TempCo=15%, Temperature Characteristic=X7R, Tolerance_%=10%, ValueDisplayed=4.7uF
C15 C16 C17 C18 C19 C20 C42: library part CMP-0079993-1, "CAP, CERM, 0.01 µF, 100 V,+/- 10%, X7R, 0603", Cap_Case=0603, Manufacturer="Wurth Elektronik", Supplier Part Number 1=45AC8565, TempCo=X7R, Tolerance_%=10%, Value2=100V, ValueDisplayed=0.01µF
C29: library part CMP-0077895-3, "CAP, CERM, 0.22 µF, 100 V,+/- 20%, X7S, AEC-Q200 Grade 1, 0603", Cap_Case=0603, Manufacturer="Taiyo Yuden", Supplier Part Number 1=587-5013-1-ND, TempCo=X7S, Tolerance_%=20%, Value2=100V, ValueDisplayed=0.22µF
C31: library part CMP-0079247-1, "CAP, CERM, 4700 pF, 100 V,+/- 10%, X7R, AEC-Q200 Grade 1, 0603", Cap_Case=0603, Manufacturer=MuRata, Supplier Part Number 1=490-4930-1-ND, TempCo=X7R, Tolerance_%=10%, Value2=100V, ValueDisplayed=4700pF
C32 C33 C34 C35: library part CMP-0082266-1, "CAP, CERM, 22 µF, 25 V,+/- 10%, X7R, 1210", Cap_Case=1210, Manufacturer=Kemet, Supplier Part Number 1=399-11958-1-ND, TempCo=X7R, Tolerance_%=10%, Value1="0.001 ohm", Value2=25V, ValueDisplayed=22µF
C36: library part CMP-0010917-1, "CAP, AL, 33 uF, 25 V, +/- 20%, 1.6 ohm, SMD", Cap_Case=F60, Manufacturer=Chemi-Con, Supplier Part Number 1=565-2299-1-ND, Tolerance_%=20%, Value1="1.6 ohm", Value2=25V, ValueDisplayed=33uF
C38: library part CMP-0007068-4, "CAP, CERM, 2.2 uF, 16 V, +/- 20%, X7S, AEC-Q200 Grade 1, 0603", Cap_Case=0603, Manufacturer=TDK, Supplier Part Number 1=445-16105-1-ND, TempCo=X7S, Tolerance_%=20%, Value1=Unknown, Value2=16V, ValueDisplayed=2.2uF
C39: library part CMP-0007237-4, "CAP, CERM, 100 pF, 100 V, +/- 5%, C0G/NP0, 0603", Cap_Case=0603, Manufacturer=MuRata, Supplier Part Number 1=490-1351-1-ND, TempCo=C0G/NP0, Tolerance_%=5%, Value1=Unknown, Value2=100V, ValueDisplayed=100pF
C40: library part CMP-0006876-4, "CAP, CERM, 0.012 uF, 25 V, +/- 5%, C0G/NP0, 0603", Cap_Case=0603, Manufacturer=Kemet, Supplier Part Number 1=399-8997-1-ND, TempCo=C0G/NP0, Tolerance_%=5%, Value1=Unknown, Value2=25V, ValueDisplayed=0.012uF
C41: library part CMP-0006754-4, "CAP, CERM, 1 uF, 25 V, +/- 10%, X7R, 0603", Cap_Case=0603, Manufacturer=AVX, Supplier Part Number 1=478-10046-1-ND, TempCo=X7R, Tolerance_%=10%, Value1=Unknown, Value2=25V, ValueDisplayed=1uF
C43: library part CMP-0080062-1, "CAP, CERM, 47 pF, 50 V,+/- 5%, C0G/NP0, AEC-Q200 Grade 0, 0603", Cap_Case=0603, Manufacturer=TDK, Supplier Part Number 1=445-12417-1-ND, TempCo=C0G/NP0, Tolerance_%=5%, Value2=50V, ValueDisplayed=47pF
C45: library part CMP-0007166-4, "CAP, CERM, 680 pF, 25 V, +/- 5%, C0G/NP0, 0603", Cap_Case=0603, Manufacturer=MuRata, Supplier Part Number 1=GRM1885C1E681JA01D-ND, TempCo=C0G/NP0, Tolerance_%=5%, Value1=Unknown, Value2=25V, ValueDisplayed=680pF
FB1: library part CMP-0097847-1, "100 Ohms @ 100 MHz 1 Power Line Ferrite Bead 3312 (8531 Metric) 10A 4mOhm", Digikey Part Number=732-78279225101CT-ND, Impedance At Frequency="100Ω @ 100MHz", Manufacturer="Wurth Electronics", Mouser Part Number=710-78279225101, Operating Temperature Range="-55°C to +125°C", Tolerance_%=25%
FID1 FID2 FID3 FID4 FID5 FID6: library part CMP-0077181-1, "Fiducial mark.  There is nothing to buy or mount.", Manufacturer=N/A
H1 H2 H3 H4: library part CMP-0003617-1, "Machine Screw, Round, #4-40 x 1/4, Nylon, Philips panhead", Manufacturer="B&F Fastener Supply", Supplier Part Number 1=H542-ND
H5 H6 H7 H8: library part CMP-0003611-1, "Standoff, Hex, 1\"L #4-40 Nylon", Manufacturer=Keystone, Supplier Part Number 1=36-1902E-ND
J1 J5: library part CMP-0095936-2, Current_A=16A, Digikey Part Number=732-691253510002-ND, Manufacturer="Wurth Electronics", Mouser Part Number=710-691253510002, Operating Temperature Range="-30°C to +120°C", Voltage_V=300V
J2: library part CMP-0095936-2, "2 Position Wire to Board Terminal Block Horizontal with Board 0.200\" (5.08mm) Through Hole", Current_A=16A, Digikey Part Number=732-691253510002-ND, Manufacturer="Wurth Electronics", Mouser Part Number=710-691253510002, Operating Temperature Range="-30°C to +120°C", Voltage_V=300V
J3 J4 J6 J7: library part CMP-0054796-4, "Header, 2.54 mm, 3x1, Gold, TH", Manufacturer="Wurth Elektronik", Supplier Part Number 1=732-5316-ND
J8: library part CMP-0075454-1, "Header, 100mil, 11x1, Gold, TH", Color=Black, Current_A=6.3A, Manufacturer=Samtec, Supplier Part Number 1=SAM1029-11-ND, Voltage_V=550V
J9: library part CMP-0055161-1, Manufacturer=Keystone, Supplier Part Number 1=36-1040-ND
L1: library part CMP-0120523-1, "2.2 µH Shielded Molded Inductor 11 A 11.5mOhm Max 1616 (4040 Metric)", Digikey Part Number=2457-XGL4040-222MEC-ND, Manufacturer=Coilcraft, Operating Temperature Range=to, Self Resonant Frequency=37MHz, Test Frequency=1MHz, Tolerance_%=20%
L2: library part CMP-0085405-1, "Coupled inductor, 0.015 ohm, AEC-Q200 Grade 1, SMD", Manufacturer=TDK
L2A: library part CMP-0094052-1, "9 µH @ 100 kHz 2 Line Common Mode Choke Surface Mount 700 Ohms @ 100 MHz 8A DCR 6mOhm", Digikey Part Number=732-744237701CT-ND, Impedance At Frequency="700Ω @ 100MHz", Manufacturer="Wurth Electronics", Mouser Part Number=710-744237701, Operating Temperature Range="-40°C to +125°C", Test Frequency=100kHz, Tolerance_%=50%
L4: library part CMP-0120488-1, "6.8 µH Shielded Molded Inductor 14.8 A 12.5mOhm Max Nonstandard", Digikey Part Number=4652-XGL1060-682MEC-ND, Manufacturer=Coilcraft, Operating Temperature Range=to, Self Resonant Frequency=14MHz, Test Frequency=1MHz, Tolerance_%=20%
Logo1: library part CMP-0074837-2, "IEC 61010-1 Hot Surface Warning", Manufacturer="Texas Instruments"
Logo2: library part CMP-0074844-1
Logo3: library part CMP-0074838-1, "Texas Instrument Corporate Signature"
Logo4: library part CMP-0074847-1, "FCC_disclaimer"
Logo5: library part CMP-0074769-3, Manufacturer="Texas Instruments"
NT1: library part CMP-0078142-6, "Single point connection between nets.", Manufacturer=N/A
Q1 Q2: library part CMP-0121870-1, "N-Channel 80 V 13A (Ta), 57A (Tc) 3.7W (Ta), 73W (Tc) Surface Mount 5-DFN (5x6) (8-SOFL)", Digikey Part Number=NTMFS6H848NT1GOSCT-ND, Drain To Source Breakdown Voltage=80V, Input Capacitace At Vds="1180pF @ 40V", Manufacturer=onsemi, Mouser Part Number=863-NTMFS6H848NT1G, Operating Temperature Range="-55°C to +175°C", Power_W=3.7W, Pulse Drain Current=308A, Typ Forward Diode Voltage=0.8V
R1: library part CMP-0018760-2, "RES, 0, 5%, 0.25 W, AEC-Q200 Grade 0, 1206", Manufacturer=Vishay-Dale, Power_W=250mW, Supplier Part Number 1=541-2239-1-ND, TempCo=ppm/C, Tolerance_%=5%, Value2=0.25W, Value_Code=0000, ValueDisplayed=0
R2 R5 R12 R21: library part CMP-0025885-5, "RES, 0, 5%, 0.1 W, 0603", Manufacturer=Yageo, Power_W=100mW, Supplier Part Number 1=311-0.0GRCT-ND, TempCo="200 ppm/C", Tolerance_%=5%, Value2=0.1W, Value_Code=0000, ValueDisplayed=0
R3 R4 R19: library part CMP-0022735-5, "RES, 100 k, 1%, 0.1 W, 0603", Manufacturer=Yageo, Power_W=100mW, Supplier Part Number 1=311-100KHRCT-ND, TempCo="100 ppm/C", Tolerance_%=1%, Value2=0.1W, Value_Code=100k
R6: library part CMP-0015079-2, "RES, 0.005, 1%, 2 W, 2512 WIDE", Manufacturer=Ohmite, Power_W=2W, Supplier Part Number 1=FCSL64R005FERCT-ND, TempCo="75 ppm/C", Tolerance_%=1%, Value_Code=5L000, ValueDisplayed=0.005
R7: library part CMP-0023180-5, "RES, 54.9 k, 1%, 0.1 W, 0603", Manufacturer=Yageo, Power_W=100mW, Supplier Part Number 1=311-54.9KHRCT-ND, TempCo="100 ppm/C", Tolerance_%=1%, Value2=0.1W, Value_Code=54k9, ValueDisplayed=54.9k
R8: library part CMP-0022008-4, "RES, 110 k, 1%, 0.1 W, AEC-Q200 Grade 0, 0603", Manufacturer=Vishay-Dale, Power_W=100mW, Supplier Part Number 1=541-110KHCT-ND, TempCo="100 ppm/C", Tolerance_%=1%, Value2=0.1W, Value_Code=110k
R9 R10 R11: library part CMP-0022707-2, "RES, 49.9, 1%, 0.1 W, AEC-Q200 Grade 0, 0603", Manufacturer=Panasonic, Power_W=100mW, Supplier Part Number 1=P49.9HCT-ND, TempCo="100 ppm/C", Tolerance_%=1%, Value2=0.1W, Value_Code=49R9, ValueDisplayed=49.9
R13: library part CMP-0023155-5, "RES, 4.99 k, 1%, 0.1 W, 0603", Manufacturer=Yageo, Power_W=100mW, Supplier Part Number 1=311-4.99KHRCT-ND, TempCo="100 ppm/C", Tolerance_%=1%, Value2=0.1W, Value_Code=4k99, ValueDisplayed=4.99k
R14: library part CMP-0023311-5, "RES, 8.87 k, 1%, 0.1 W, 0603", Manufacturer=Yageo, Power_W=100mW, Supplier Part Number 1=311-8.87KHRCT-ND, TempCo="100 ppm/C", Tolerance_%=1%, Value2=0.1W, Value_Code=8k87, ValueDisplayed=8.87k
R15: library part CMP-0023335-5, "RES, 9.53 k, 1%, 0.1 W, 0603", Manufacturer=Yageo, Power_W=100mW, Supplier Part Number 1=311-9.53KHRCT-ND, TempCo="100 ppm/C", Tolerance_%=1%, Value2=0.1W, Value_Code=9k53, ValueDisplayed=9.53k
R16: library part CMP-0022994-5, "RES, 2.67 k, 1%, 0.1 W, 0603", Manufacturer=Yageo, Power_W=100mW, Supplier Part Number 1=311-2.67KHRCT-ND, TempCo="100 ppm/C", Tolerance_%=1%, Value2=0.1W, Value_Code=2k67, ValueDisplayed=2.67k
R17: library part CMP-0023066-5, "RES, 38.3 k, 1%, 0.1 W, 0603", Manufacturer=Yageo, Power_W=100mW, Supplier Part Number 1=311-38.3KHRCT-ND, TempCo="100 ppm/C", Tolerance_%=1%, Value2=0.1W, Value_Code=38k3, ValueDisplayed=38.3k
R18: library part CMP-0023205-5, "RES, 5.90 k, 1%, 0.1 W, 0603", Manufacturer=Yageo, Power_W=100mW, Supplier Part Number 1=311-5.90KHRCT-ND, TempCo="100 ppm/C", Tolerance_%=1%, Value2=0.1W, Value_Code=5k90, ValueDisplayed=5.90k
R20: library part CMP-0080492-1, "RES, 49.9, 1%, 0.1 W, 0603", Manufacturer="TT Electronics/IRC", Power_W=100mW, TempCo="100 ppm/C", Tolerance_%=1%, Value2=0.1W, Value_Code=49R9, ValueDisplayed=49.9
R22: library part CMP-0023277-5, "RES, 7.15 k, 1%, 0.1 W, 0603", Manufacturer=Yageo, Power_W=100mW, Supplier Part Number 1=311-7.15KHRCT-ND, TempCo="100 ppm/C", Tolerance_%=1%, Value2=0.1W, Value_Code=7k15, ValueDisplayed=7.15k
R23: library part CMP-0025899-5, "RES, 1.0 k, 5%, 0.1 W, 0603", Manufacturer=Yageo, Power_W=100mW, Supplier Part Number 1=311-1.0KGRCT-ND, TempCo="100 ppm/C", Tolerance_%=5%, Value2=0.1W, Value_Code=1k00, ValueDisplayed=1.0k
SH-J1 SH-J2 SH-J3 SH-J4: library part CMP-0078738-1, "Single Operation 2.54mm Pitch Open Top Jumper Socket", Manufacturer=Harwin, Supplier Part Number 1=952-2881-ND
TP1 TP3: library part CMP-0055137-2, "Test Point, Miniature, Red, TH", Color=Red, Manufacturer="Keystone Electronics", Supplier Part Number 1=36-5000-ND
TP2 TP4: library part CMP-0055138-2, "Test Point, Miniature, Black, TH", Color=Black, Manufacturer="Keystone Electronics", Supplier Part Number 1=36-5001-ND
U1: library part CMP-0120283-1, "80V Synchronous Buck Controller with Constant Current Constant Voltage Regulation", Manufacturer="Texas Instruments", Max Supply Voltage=80V, Min Supply Voltage=5V, Nominal Supply Current=125uA, Operating Temperature Range="-40°C to +150°C", Output Voltage=0.8-80V, Switching Frequency=100-2200kHz
ZZ1: library part CMP-0077236-1
ZZ2: library part CMP-0077237-1
ZZ3: library part CMP-0077238-1
ZZ4 ZZ5 ZZ6 ZZ7: library part CMP-0077238-1, "These assemblies must comply with workmanship standards IPC-A-610 Class 2, unless otherwise specified."

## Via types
v1: diameter 22, hole 10, Top Layer to Bottom Layer, tented both sides, 318 vias
v2: diameter 24, hole 10, Top Layer to Bottom Layer, tented both sides, 178 vias
v3: diameter 19.68, hole 7.87, Top Layer to Bottom Layer, tented both sides, 15 vias
v4: diameter 24, hole 8, Top Layer to Bottom Layer, tented both sides, 2 vias

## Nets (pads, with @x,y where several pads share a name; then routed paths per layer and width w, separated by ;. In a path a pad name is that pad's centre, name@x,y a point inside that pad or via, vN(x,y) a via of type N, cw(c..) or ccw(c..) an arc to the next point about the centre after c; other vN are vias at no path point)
AGND: C43.2 C44.1 J3.1 J4.3 J7.3 J8.8 J8.10 J9.1 NT1.2 R14.1 R15.1 R17.1 R18.1 R21.2 R22.1 U1.5 | length 2613.1
  Top Layer w9: U1.5@1663.39,1764.76 NT1.2@1663.39,1778.13
  Top Layer w10: 1663.39,1740.92 U1.5@1663.39,1764.76
  Top Layer w12: 1663.36,1571.34 1663.36,1740.89
  Top Layer w24: J4.3@1201.57,1491.43 1285.87,1491.43 1341.06,1546.62 1433.25,1546.62 ; J3.1@1201.57,2049.89 1205.16,2053.49 1403,2053.49 1406.6,2057.09 1409.91,2053.77 1490.33,2053.77 1500.67,2043.43 R14.1@1589.95,2043.43 ; v1(1466.6,2775.59) v1@1467.9,2776.9 ; v1@1469.6,2778.59 1721.62,2778.59 ; J8.10@1721.62,2873.19 1721.62,2778.59 ; J8.8@1922.07,2872.83 1922.07,2799.2 1901.45,2778.59 1721.62,2778.59
  Top Layer w32: J7.3@1537.67,1397.83 1537.67,1562.08 1538.43,1562.84
  Signal Layer 2 w24: J9.1@1395.26,2058.42 1395.26,2704.25 v1(1466.6,2775.59) ; J9.1@1395.61,2056.1 1395.61,1875.32 v1(1417.39,1853.55)
BIAS: C41.1 J8.2 U1.14 | length 1414.7
  Top Layer w10: U1.14@1683.07,1894.69 1683.07,1916.77 1699.42,1933.12 C41.1@1699.42,1985.51 1700.98,1987.07 1725.29,1987.07 1737.09,1998.87 v1(1770.75,1998.87)
  Signal Layer 2 w10: v1(1770.75,1998.87) 1953.64,2181.76 1953.64,2322.97 2100.91,2470.24 2192.69,2470.24 2522.44,2799.98 J8.2@2522.44,2874.02
COMP: C40.1 C43.1 J8.5 U1.3 | length 1982
  Top Layer w10: C43.1@1574.53,1624.85 1574.53,1666.93 C40.1@1573.54,1667.92 1583.76,1678.14 1597.02,1678.14 v1(1612.78,1693.9) 1612.78,1697.15 1625.83,1710.19 1625.83,1747.5 1624.09,1749.23 1624.09,1764.69 U1.3@1624.02,1764.76
  Signal Layer 2 w10: v1(1609.65,2732.71) 1609.65,1963.36 1606.07,1959.78 1606.07,1940 1606.12,1939.95 1606.12,1898.05 1586.46,1878.39 1586.46,1720.22 1611.97,1694.7 v1@1612.78,1694.7 ; v1(2173.35,2726.38) 2176.41,2726.38 2222.44,2772.41 J8.5@2222.44,2874.02
  Signal Layer 3 w10: v1(1609.65,2732.71) 1629.43,2752.49 2147.24,2752.49 v1(2173.35,2726.38)
"EMI GND": C2.2 C3.2 C4.2 J2.2 L2.3 L2A.4 | length 17.3
  Bottom Layer w20: C2.2@382.18,2619.43 C2.2@383.7,2620.94 ; 492.13,2221.3 502.85,2232.02
EN: J8.11 R3.1 R14.2 U1.17 | length 1110.6
  Top Layer w10: v1@1542.74,1989.49 v1(1545.98,1989.49) 1588.78,1989.49 R14.2@1589.95,1988.31 ; R14.2@1589.95,1986.19 R3.1@1642.51,1986.19 ; R14.2@1597.47,1977.85 1600.56,1974.76 1600.56,1944.1 1624.02,1920.64 U1.17@1624.02,1894.69
  Signal Layer 2 w10: v1(1545.98,1989.49) 1545.98,2797.56 J8.11@1622.44,2874.02
FB: C45.2 J7.2 J8.4 R16.1 R19.1 R22.2 U1.4 | length 2362.4
  Top Layer w10: R16.1@1588.14,1192.73 1590.59,1190.29 v1(1623.25,1190.29) ; C45.2@1589.29,1307.09 1636.87,1307.09 1637.67,1306.29 J7.2@1637.67,1397.83 ; R22.2@1629.71,1625.68 1633.86,1629.83 v1(1633.86,1660.79) 1633.86,1672.09 1643.7,1681.93 U1.4@1643.7,1764.76
  Signal Layer 2 w10: v1(1623.25,1190.29) 1637.2,1204.24 J7.2@1637.67,1397.83 ; J7.2@1637.67,1384.02 1637.67,1656.98 v1(1633.86,1660.79) 1636.15,1663.08 1636.15,1683.51 1636.65,1684.01 1636.65,1710.34 1604.33,1742.67 1604.33,1870.99 1647.47,1914.13 1688.9,1914.13 1731.68,1956.91 1731.68,2060.04 1894.19,2222.55 1894.19,2391.73 2322.44,2819.98 J8.4@2322.44,2874.02
ILIM/IMON: C42.1 J8.9 R15.2 U1.6 | length 2462.6
  Top Layer w10: U1.6@1683.07,1764.76 1683.07,1639.49 1683.67,1638.88 1683.67,1633.63 R15.2@1694.42,1622.88 ; R15.2@1696.52,1622.91 1704.76,1614.67 1733.31,1614.67 1735.17,1612.81 1736.15,1612.81 1746.9,1602.07 C42.1@1746.9,1601.08 1755.11,1609.29 v1(1755.11,1641.57)
  Signal Layer 2 w10: v1@1320.78,1642.56 1320.78,1645.81 1323.21,1648.24 1322.85,2523.97 1322.85,2551.45 1324.99,2553.59 v1(1324.99,2591.28) ; v1(1821.62,2593.24) 1821.62,2648.34 1822.44,2649.16 J8.9@1822.44,2874.02
  Signal Layer 3 w10: v1(1322.15,1642.74) 1322.15,1640.7 1388.9,1573.95 1689.27,1573.95 v1@1752.13,1636.8 ; v1@1326.96,2593.24 v1(1821.62,2593.24)
ISET: J8.7 R13.1 | length 110.6
  Top Layer w10: R13.1@2022.44,2763.45 J8.7@2022.44,2874.02
NetC1_1: C1.1 R1.1 | length 194.8
  Bottom Layer w24: C1.1@1111,790.62 R1.1@1305.8,790.62
NetC4_1: C4.1 FB1.2 L2.4 L2A.2
NetC5_1: C5.1 C6.1 C9.2 C10.2 C11.2 C12.2 L1.1 L2.1 L2A.1
NetC29_2: C29.2 R2.1 U1.10 | length 116.5
  Top Layer w10: U1.10@1757.87,1800.2 1814.53,1800.2 C29.2@1817.99,1796.74 R2.1@1872.94,1796.74
NetC30_1: C30.1 L4.1 Q1.1 Q1.2 Q1.3 Q2.5-6 R8.1 U1.12 | length 767.2
  Top Layer w10: U1.12@1742.13,1894.69 1756.89,1894.69 1762.8,1900.59 1787.66,1900.59 C30.1@1790.55,1903.49 1790.55,1902.5 1828.79,1864.27 ; L4.1@2404.53,1821.48 L4.1@2404.99,1821.95 ; L4.1@2405.47,1780.51 2469.26,1780.51 2527.76,1839.02 2527.76,2088.81 2521.39,2095.19 2521.39,2097.14 2513.44,2105.09 R8.1@2510.5,2105.09
  Top Layer w24: 1828.79,1864.27 Q1.1@2066.73,1864.27
NetC30_2: C30.2 R5.2 | length 80.9
  Top Layer w10: R5.2@1798.31,1948.33 R5.2@1806.59,1948.33 ; R5.2@1798.43,1956.5 R5.2@1806.59,1948.33 ; C30.2@1845.67,1903.49 1845.67,1904.47 1809.18,1940.97 1809.18,1945.75 R5.2@1806.59,1948.33
NetC31_1: C31.1 R8.2 R9.2 | length 203.6
  Top Layer w10: R8.2@2510.5,2160.2 2563.67,2160.2 C31.1@2564.97,2161.5 ; C31.1@2566.47,2163 2567.45,2163 2586.42,2144.04 2688.83,2144.04 2701.14,2156.34 R9.2@2701.14,2157.33
NetC31_2: C31.2 L4.2 R6.1 R10.2 R11.1 | length 832
  Top Layer w10: L4.2@2667.28,1780.51 2604.18,1780.51 2545.64,1839.06 2545.64,2089.89 2552.88,2097.14 2555.72,2097.14 C31.2@2566.47,2107.89 2567.45,2107.89 2578.2,2118.63 2578.2,2119.62 2584.74,2126.16 2680.89,2126.16 2692.2,2114.85 2693.19,2114.85 2703.94,2104.1 R10.2@2703.94,2103.12 ; R6.1@2836.61,1821.95 2875.77,1821.95 2883.86,1830.03 2883.86,1830.31 v1(2905.91,1852.36) ; v1(2905.91,1978.92) R11.1@2905.91,2015.41
  Signal Layer 3 w10: v1(2905.91,1852.36) 2905.91,1855.61 2898.48,1863.04 2898.48,1968.24 2905.91,1975.67 v1(2905.91,1978.92)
